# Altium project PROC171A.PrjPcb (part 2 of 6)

## Sheet PROC171_AM263P_2_Clock_Reset_Boot_JTAG.SchDoc
size 431 x 279 mm; Date: Not shown in title block; ApprovedBy: Not shown in title block; CheckedBy: Not shown in title block; Author: Not shown in title block; CompanyName: Not shown in title block; Engineer: Srinivas; Organization: Not shown in title block; Address1: Not shown in title block; Address2: Not shown in title block; Address3: Not shown in title block; Address4: Not shown in title block; DocumentNumber: 6; Revision: Use project parameter SCH_Rev; SheetNumber: 6; SheetTotal: 27; PageSetup: Record=PageOptions¦CenterHorizontal=True¦CenterVertical=True¦PrintScale=1.00¦XCorrection=1.00¦YCorrection=1.00¦PrintKind=0¦BorderSize=5000000¦LeftOffset=0¦BottomOffset=0¦Orientation=2¦PaperLength=1000¦PaperWidth=1000¦Scale=100¦PaperSource=15¦PrintQuality=600¦MediaType=1¦DitherType=10¦PaperKind=Letter¦PrintScaleMode=1
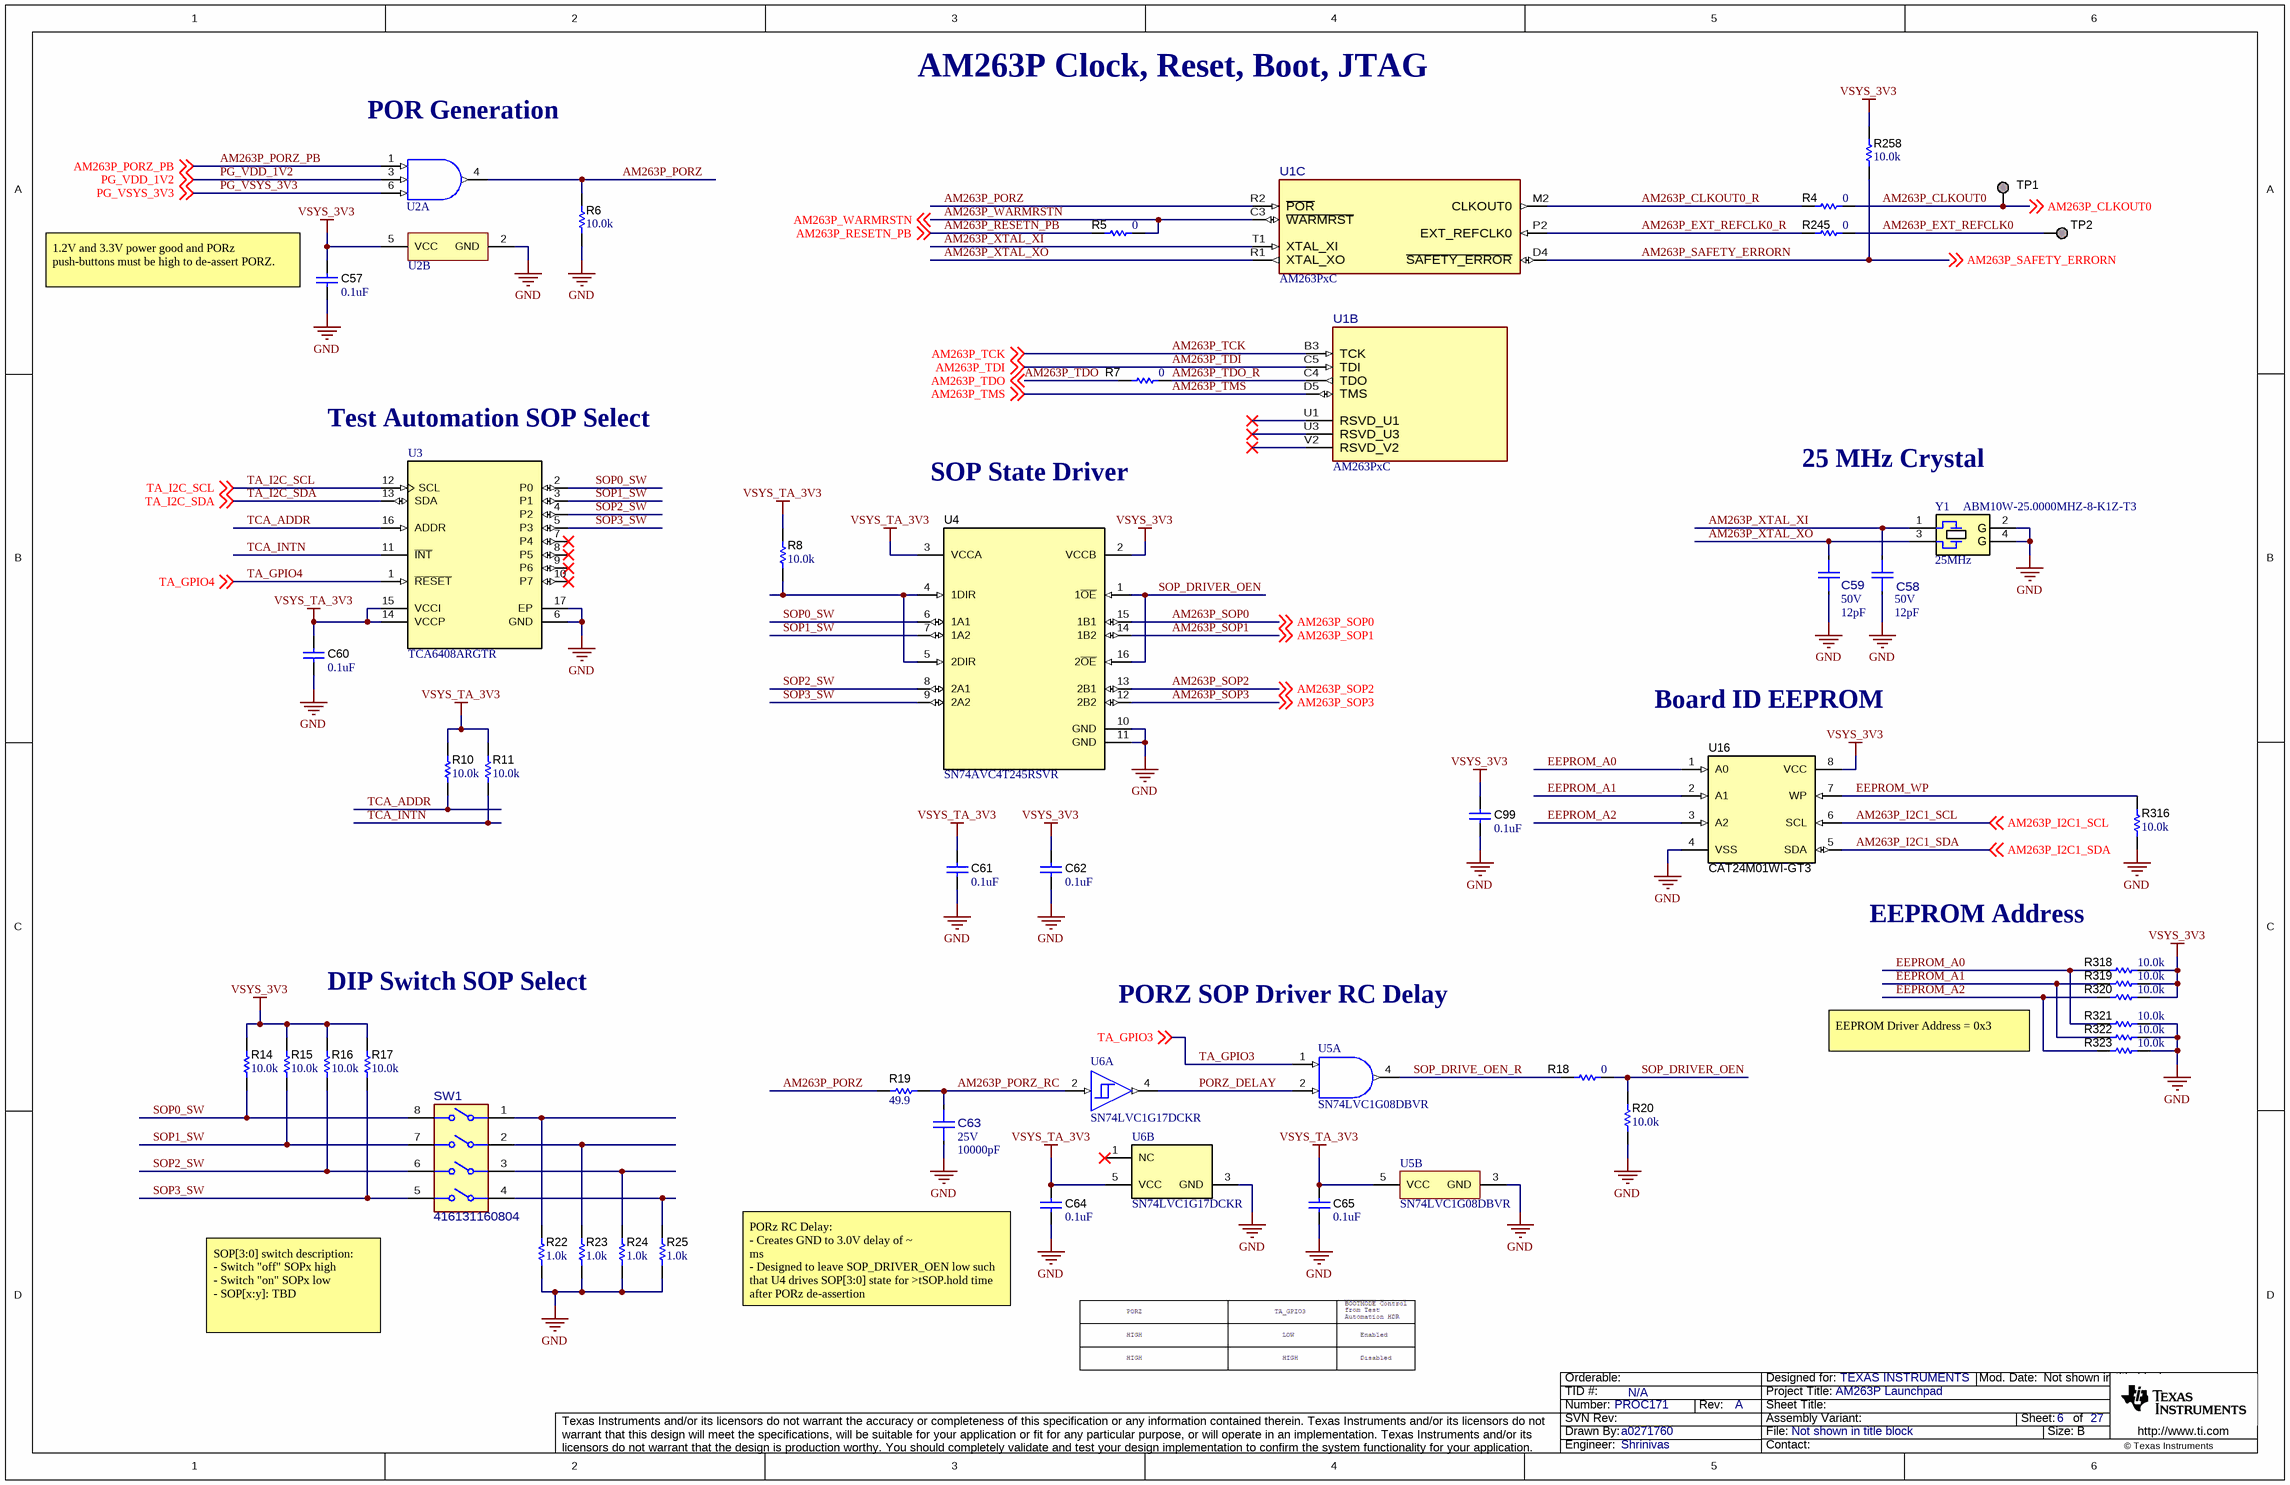
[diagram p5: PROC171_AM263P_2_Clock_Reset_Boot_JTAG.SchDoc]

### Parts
C57  ValueDisplayed: 0.1uF  [0402]  (hidden comment: GRM155R71E104KE14D)
C58  VDC_V: 50V  ValueDisplayed: 12pF  [FP-GJM1555C1H120JB01D_0402-MFG]  (hidden comment: GJM1555C1H120JB01D)
C59  VDC_V: 50V  ValueDisplayed: 12pF  [FP-GJM1555C1H120JB01D_0402-MFG]  (hidden comment: GJM1555C1H120JB01D)
C60  ValueDisplayed: 0.1uF  [0402]  (hidden comment: GRM155R71E104KE14D)
C61  ValueDisplayed: 0.1uF  [0402]  (hidden comment: GRM155R71E104KE14D)
C62  ValueDisplayed: 0.1uF  [0402]  (hidden comment: GRM155R71E104KE14D)
C63  VDC_V: 25V  ValueDisplayed: 10000pF  [FP-GRM1555C1E103JE01D_0402-MFG]  (hidden comment: GRM1555C1E103JE01D)
C64  ValueDisplayed: 0.1uF  [0402]  (hidden comment: GRM155R71E104KE14D)
C65  ValueDisplayed: 0.1uF  [0402]  (hidden comment: GRM155R71E104KE14D)
C99  ValueDisplayed: 0.1uF  [0402]  (hidden comment: GRM155R71E104KE14D)
R4  value 0  [0402L]  (hidden comment: ERJ-2GE0R00X)
R5  ValueDisplayed: 0  [0402]  (hidden comment: ERJ-2GE0R00X)
R6  ValueDisplayed: 10.0k  [0402]  (hidden comment: ERJ-2RKF1002X)
R7  value 0  [0402L]  (hidden comment: ERJ-2GE0R00X)
R8  ValueDisplayed: 10.0k  [0402]  (hidden comment: ERJ-2RKF1002X)
R10  ValueDisplayed: 10.0k  [0402]  (hidden comment: ERJ-2RKF1002X)
R11  ValueDisplayed: 10.0k  [0402]  (hidden comment: ERJ-2RKF1002X)
R14  ValueDisplayed: 10.0k  [0402]  (hidden comment: ERJ-2RKF1002X)
R15  ValueDisplayed: 10.0k  [0402]  (hidden comment: ERJ-2RKF1002X)
R16  ValueDisplayed: 10.0k  [0402]  (hidden comment: ERJ-2RKF1002X)
R17  ValueDisplayed: 10.0k  [0402]  (hidden comment: ERJ-2RKF1002X)
R18  ValueDisplayed: 0  [0402]  (hidden comment: ERJ-2GE0R00X)
R19  ValueDisplayed: 49.9  [0402]  (hidden comment: ERJ-2RKF49R9X)
R20  ValueDisplayed: 10.0k  [0402]  (hidden comment: ERJ-2RKF1002X)
R22  ValueDisplayed: 1.0k  [0402]  (hidden comment: ERJ-2GEJ102X)
R23  ValueDisplayed: 1.0k  [0402]  (hidden comment: ERJ-2GEJ102X)
R24  ValueDisplayed: 1.0k  [0402]  (hidden comment: ERJ-2GEJ102X)
R25  ValueDisplayed: 1.0k  [0402]  (hidden comment: ERJ-2GEJ102X)
R245  value 0  [0402L]  (hidden comment: ERJ-2GE0R00X)
R258  ValueDisplayed: 10.0k  [0402]  (hidden comment: ERJ-2RKF1002X)
R316  ValueDisplayed: 10.0k  [0402]  (hidden comment: ERJ-2RKF1002X)
R318  ValueDisplayed: 10.0k  [0402]  (hidden comment: ERJ-2RKF1002X)
R319  ValueDisplayed: 10.0k  [0402]  (hidden comment: ERJ-2RKF1002X)
R320  ValueDisplayed: 10.0k  [0402]  (hidden comment: ERJ-2RKF1002X)
R321  ValueDisplayed: 10.0k  [0402]  (hidden comment: ERJ-2RKF1002X)
R322  ValueDisplayed: 10.0k  [0402]  (hidden comment: ERJ-2RKF1002X)
R323  ValueDisplayed: 10.0k  [0402]  (hidden comment: ERJ-2RKF1002X)
SW1  416131160804  [FP-416131160804_SMT_SW-MFG]
TP1  TP_SM_1MM  [TP_SM_1MM]  (value not drawn)  (no BOM)
TP2  TP_SM_1MM  [TP_SM_1MM]  (value not drawn)  (no BOM)
U1  AM263PxC  [ZCZ0324A-MFG]  (parts B,C of 13)
U2  SN74LVC1G11DBVR  [DBV0006A_N]  (value not drawn)  (parts A,B of 2)
U3  TCA6408ARGTR  [RGT0016A]
U4  SN74AVC4T245RSVR  [RSV0016A]
U5  SN74LVC1G08DBVR  [DBV0005A_N]  (parts A,B of 2)
U6  SN74LVC1G17DCKR  [DCK0005A_N]  (parts A,B of 2)
U16  CAT24M01WI-GT3  [SOIC-8]
Y1  Frequency_Fixed: 25MHz  PartNumber: ABM10W-25.0000MHZ-8-K1Z-T3  [Abracon_ABM10W]  (hidden comment: ABM10W-25.0000MHZ-4-D1X-T3)

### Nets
GND: C57.1 C58.1 C59.1 C60.1 C61.1 C62.1 C63.1 C64.1 C65.1 C99.1 R6.1 R20.2 R22.1 R23.1 R24.1 R25.1 R316.2 R321.1 R322.1 R323.1 U2.2(GND) U3.6(GND) U3.17(EP) U4.10(GND) U4.11(GND) U5.3(GND) U6.3(GND) U16.4(VSS) Y1.2(GND) Y1.4(GND)
VSYS_3V3: C57.2 C62.2 C99.2 R14.1 R15.1 R16.1 R17.1 R258.2 R318.1 R319.1 R320.1 U2.5(VCC) U4.2(VCCB) U16.8(VCC)
VSYS_TA_3V3: C60.2 C61.2 C64.2 C65.2 R8.1 R10.1 R11.1 U3.14(VCCP) U3.15(VCCI) U4.3(VCCA) U5.5(VCC) U6.5(VCC)
AM263P_CLKOUT0: R4.2 TP1.1 ; off-sheet AM263P_CLKOUT0
AM263P_CLKOUT0_R: R4.1 U1.M2(CLKOUT0)
AM263P_EXT_REFCLK0: R245.2 TP2.1
AM263P_EXT_REFCLK0_R: R245.1 U1.P2(EXT_REFCLK0)
AM263P_I2C1_SCL: U16.6(SCL) ; off-sheet AM263P_I2C1_SCL
AM263P_I2C1_SDA: U16.5(SDA) ; off-sheet AM263P_I2C1_SDA
AM263P_PORZ: R6.2 R19.1 U1.R2(~{POR}) U2.4(Y)
AM263P_PORZ_PB: U2.1(A) ; off-sheet AM263P_PORZ_PB
AM263P_PORZ_RC: C63.2 R19.2 U6.2(A)
AM263P_RESETN_PB: R5.1 ; off-sheet AM263P_RESETN_PB
AM263P_SAFETY_ERRORN: R258.1 U1.D4(~{SAFETY_ERROR}) ; off-sheet AM263P_SAFETY_ERRORN
AM263P_SOP0: U4.15(1B1) ; off-sheet AM263P_SOP0
AM263P_SOP1: U4.14(1B2) ; off-sheet AM263P_SOP1
AM263P_SOP2: U4.13(2B1) ; off-sheet AM263P_SOP2
AM263P_SOP3: U4.12(2B2) ; off-sheet AM263P_SOP3
AM263P_TCK: U1.B3(TCK) ; off-sheet AM263P_TCK
AM263P_TDI: U1.C5(TDI) ; off-sheet AM263P_TDI
AM263P_TDO: R7.1 ; off-sheet AM263P_TDO
AM263P_TDO_R: R7.2 U1.C4(TDO)
AM263P_TMS: U1.D5(TMS) ; off-sheet AM263P_TMS
AM263P_WARMRSTN: R5.2 U1.C3(~{WARMRST}) ; off-sheet AM263P_WARMRSTN
AM263P_XTAL_XI: C58.2 U1.T1(XTAL_XI) Y1.1
AM263P_XTAL_XO: C59.2 U1.R1(XTAL_XO) Y1.3
EEPROM_A0: R318.2 R321.2 U16.1(A0)
EEPROM_A1: R319.2 R322.2 U16.2(A1)
EEPROM_A2: R320.2 R323.2 U16.3(A2)
EEPROM_WP: R316.1 U16.7(WP)
PG_VDD_1V2: U2.3(B) ; off-sheet PG_VDD_1V2
PG_VSYS_3V3: U2.6(C) ; off-sheet PG_VSYS_3V3
PORZ_DELAY: U5.2(B) U6.4(Y)
SOP0_SW: R14.2 SW1.8 U3.2(P0) U4.6(1A1)
SOP1_SW: R15.2 SW1.7 U3.3(P1) U4.7(1A2)
SOP2_SW: R16.2 SW1.6 U3.4(P2) U4.8(2A1)
SOP3_SW: R17.2 SW1.5 U3.5(P3) U4.9(2A2)
SOP_DRIVE_OEN_R: R18.1 U5.4(Y)
SOP_DRIVER_OEN: R18.2 R20.1 U4.1(1~{OE}) U4.16(2~{OE})
TA_GPIO3: U5.1(A) ; off-sheet TA_GPIO3
TA_GPIO4: U3.1(~{RESET}) ; off-sheet TA_GPIO4
TA_I2C_SCL: U3.12(SCL) ; off-sheet TA_I2C_SCL
TA_I2C_SDA: U3.13(SDA) ; off-sheet TA_I2C_SDA
TCA_ADDR: R10.2 U3.16(ADDR)
TCA_INTN: R11.2 U3.11(~{INT})
NetR8_2: R8.2 U4.4(1DIR) U4.5(2DIR)
NetR22_2: R22.2 SW1.1
NetR23_2: R23.2 SW1.2
NetR24_2: R24.2 SW1.3
NetR25_2: R25.2 SW1.4

Not connected (* = marked no-connect by the designer): U1 U1(RSVD_U1)* U3(RSVD_U3)* V2(RSVD_V2)*; U3 7(P4)* 8(P5)* 9(P6)* 10(P7)*; U6 1(NC)*

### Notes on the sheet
- AM263P Clock, Reset, Boot, JTAG
- (near U2) POR Generation
- (near C57) 1.2V and 3.3V power good and PORz push-buttons must be high to de-assert PORZ.
- Test Automation SOP Select
- SOP State Driver
- 25 MHz Crystal
- Board ID EEPROM
- EEPROM Address
- DIP Switch SOP Select
- PORZ SOP Driver RC Delay
- EEPROM Driver Address = 0x3
- (near C64) PORz RC Delay:
  - Creates GND to 3.0V delay of ~
  ms
  - Designed to leave SOP_DRIVER_OEN low such that U4 drives SOP[3:0] state for >tSOP.hold time after PORz de-assertion
- SOP[3:0] switch description:
  - Switch "off" SOPx high
  - Switch "on" SOPx low
  - SOP[x:y]: TBD

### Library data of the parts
C57 C60-C62 C64 C65 C99 = CMP-0006659-2: CAP, CERM, 0.1 uF, 25 V, +/- 10%, X7R, 0402; Manufacturer: MuRata; TaMin_C: -55°C; Polarized: N; SizeAreaWB_mm2: 3; U/M: EA; Value: 0.1uF; TaMax_C: 125°C; SizeZ_mm: 0.6; SizeX_mm: 1; SizeY_mm: 0.5; Value2: 25V; Cap_F: 100nF; AEC Category: Q200; Value1: Unknown
C58 C59 = CMP-0035228-1: Multi-Layer Ceramic Capacitor 12pF C0G  ±5% 0402 Paper T/R; Manufacturer: Murata; TempCo: 30ppm/°C; SizeZ_mm: 0.55mm; AEC Qualified: No
C63 = CMP-0035343-1: Chip Multilayer Ceramic Capacitors for General Purpose, 0402, 10000pF, C0G, 30ppm/°C, 5%, 25V; Manufacturer: Murata; Value: 10nF; SizeZ_mm: 0.65mm; AEC Qualified: No
R4 R7 R245 = CMP-0026992-3: RES, 0, 5%, 0.1 W, AEC-Q200 Grade 0, 0402; Manufacturer: Panasonic; Power_W: 100mW; TempCo: 600 ppm/C; Value_Code: 0000; EIA_Code: E24; SizeX_mm: 1; SizeY_mm: 0.5; SizeZ_mm: 0.6; Value2: 0.1W; AEC Qualified: Y; VDC_V: 50V; AEC Category: Q200; SizeAreaWB_mm2: 3
R5 R18 = CMP-0026992-3: RES, 0, 5%, 0.1 W, AEC-Q200 Grade 0, 0402; Manufacturer: Panasonic; Power_W: 100mW; TempCo: 600 ppm/C; Value_Code: 0000; Value: 0; EIA_Code: E24; SizeX_mm: 1; SizeY_mm: 0.5; SizeZ_mm: 0.6; Value2: 0.1W; AEC Qualified: Y; VDC_V: 50V; AEC Category: Q200; SizeAreaWB_mm2: 3
R6 R8 R10 R11 R14-R17 R20 R258 R316 R318-R323 = CMP-0026658-1: RES, 10.0 k, 1%, 0.1 W, 0402; Manufacturer: Panasonic; Power_W: 100mW; TempCo: 100 ppm/C; Value_Code: 10k0; U/M: EA; Value: 10.0k; EIA_Code: E96; Res_ohm: 10k; SizeX_mm: 1; SizeY_mm: 0.5; SizeZ_mm: 0.6; Value2: 0.1W; VDC_V: 50V; AEC Category: Q200
R19 = CMP-0026703-1: RES, 49.9, 1%, 0.1 W, AEC-Q200 Grade 0, 0402; Manufacturer: Panasonic; Power_W: 100mW; TempCo: 100 ppm/C; Value_Code: 49R9; U/M: EA; Value: 49.9; EIA_Code: E96; SizeX_mm: 1; SizeY_mm: 0.5; SizeZ_mm: 0.6; Value2: 0.1W; AEC Qualified: Y; VDC_V: 50V; AEC Grade: 0; AEC Category: Q200
R22-R25 = CMP-0078193-1: RES, 1.0 k, 5%, 0.1 W, AEC-Q200 Grade 0, 0402; Manufacturer: Panasonic; Value_Code: 1k00; SizeArea_mm2: 0.5; AEC Qualified: Y; AEC Category: Q200; Res_ohm: 1k; Value: 1.0k; SizeZ_mm: 0.6; Green_REACh: Passed; EIA_Code: E24; TempCo: 200 ppm/C; AEC Grade: 0; Power_W: 100mW; VDC_V: 50V; Value2: 0.1W; Green_Lifecycle: Active; U/M: EA; SizeX_mm: 1
SW1 = CMP-0093176-1: Dip Switch SPST 4 Position Surface Mount Slide (Standard) Actuator 25mA 24VDC; Manufacturer: Wurth; PositionCount: 4; Electromechanical Life: 1000Cycles; Circuit: 4PST; Coil Resistance_ohm: 100mΩ; VDC_V: 24V; Standoff Height: 0mm; SizeZ_mm: 2.65mm; AEC Qualified: No
TP1 TP2 = CMP-0003825-1: 1mm Test Point, SMT; Manufacturer: Any
U1 = CMP-0001698-2: Sitara™ Microcontroller; Manufacturer: Texas Instruments; SizeZ_mm: 1.4mm; Core Architecture: ARM Cortex-R5F; Data Bus Width: 32bits; Frequency_Fixed: 200MHz; Interface: I2C,SPI,UART,CAN,LIN,Ethernet,Other; Max Supply Voltage: 3.465V; Memory Size: 2MBytes; Memory Type: RAM; Min Supply Voltage: 1.14V; Number Of Cores: 1; Number Of I/Os: 140; Number Of I2C Channels: 4; Number Of Spi Channels: 5; Number Of Uart Channels: 6; Standoff Height: 0.35mm; AEC Category: Q200; CompType: IC
U2 = CMP-0051219-1: Single 3-Input Positive-AND Gate, DBV0006A, LARGE T&R; Manufacturer: Texas Instruments; Output Type: CMOS; Voltage(Nom)(V): 1.8,2.5,3.3,5; ICC @ Nom Voltage(Max)(mA): 0.01; VCC(Min)(V): 1.65; Output Drive (IOL/IOH)(Max)(mA): 32/-32; Schmitt Trigger: No; Input Type: CMOS/TTL; VCC(Max)(V): 5.5; Gate Type: AND; Rating: Catalog; tpd @ Nom Voltage(Max)(ns): 20,7.8,6.2,4.6; Bits(#): 1; F @ Nom Voltage(Max)(Mhz): 150; Logic: True; Technology Family: LVC
U3 = CMP-0043157-2: Low-Voltage 8-Bit I2C and SMBus I/O Expander, 1.65 to 5.5 V, -40 to 85 degC, 16-pin QFN (RGT), Green (RoHS & no Sb/Br); Manufacturer: Texas Instruments; # of I/Os: 8; I2C Address: 0100 00x; Reset Input: Yes; Max Frequency(kHz): 400; VCC(Max)(V): 5.5; SubFamily: I2C IO Expander; VCC(Min)(V): 1.65
U4 = CMP-0066450-2: 4-Bit Dual-Supply Bus Transceiver with Configurable Voltage-Level Shifting and 3-State Outputs, RSV0016A (UQFN-16); Alternate Manufacturer: Texas Instruments; SizeAreaWB_mm2: 10.08; SizeZ_mm: 0.55; SizeX_mm: 1.8; SizeY_mm: 2.6; SizeArea_mm2: 4.68; CompType: IC; AEC Category: Q200; AEC Qualified: N
U5 = CMP-0051588-2: Single 2-Input Positive-AND Gate, DBV0005A, LARGE T&R; Manufacturer: Texas Instruments; Logic: True; ICC @ Nom Voltage(Max)(mA): 0.01; VCC(Min)(V): 1.65; Bits(#): 1; Rating: Catalog; Schmitt Trigger: No; Voltage(Nom)(V): 1.8,2.5,3.3,5; Output Drive (IOL/IOH)(Max)(mA): 32/-32; Gate Type: AND; tpd @ Nom Voltage(Max)(ns): 4.5,6,4,5; VCC(Max)(V): 5.5; Output Type: CMOS; F @ Nom Voltage(Max)(Mhz): 150; Input Type: CMOS/TTL; Technology Family: LVC; AEC Category: Q200; AEC Qualified: N; CompType: IC
U6 = CMP-0051704-3: Single Schmitt-Trigger Buffer, DCK0005A, LARGE T&R; Manufacturer: Texas Instruments; tpd @ Nom Voltage(Max)(ns): 11,6.5,5.5,5; Bits(#): 1; VCC(Min)(V): 1.65; F @ Nom Voltage(Max)(Mhz): 150; VCC(Max)(V): 5.5; Input Type: CMOS/TTL; Sub-Family: Non-Inverting Buffer/Driver; Output Type: CMOS; Output Drive (IOL/IOH)(Max)(mA): 32/-32; 3-State Output: No; Logic: True; ICC @ Nom Voltage(Max)(mA): 0.01; Voltage(Nom)(V): 1.8,2.5,3.3,5; Rating: Catalog; Schmitt Trigger: Yes; Technology Family: LVC; AEC Category: Q200; AEC Qualified: N; CompType: IC; SizeAreaWB_mm2: 9.3; SizeArea_mm2: 4.2; SizeX_mm: 2.1; SizeY_mm: 2.0; SizeZ_mm: 1.1
U16 = CMP-0005327-2: 1024-Kb I2C CMOS Serial EEPROM, SOIC-8; Manufacturer: ON Semiconductor; SizeAreaWB_mm2: 55.131; SizeZ_mm: 1.75; SizeX_mm: 5.99; SizeY_mm: 4.9; SizeArea_mm2: 29.351
Y1 = CMP-0084811-1: Crystal, 25 MHz, 10 ppm, 4 pF, SMD; Manufacturer: Abracon Corporation; Load Capacitance: 4 pF; TaMax_C: 85°C; SizeY_mm: 2.5; SizeAreaWB_mm2: 10.5; AEC Category: Q200; Frequency Stability: 20 ppm; SizeX_mm: 2; SizeArea_mm2: 5; SizeZ_mm: 0.6; AEC Qualified: N; TaMin_C: -40°C; Frequency Tolerance: 10 ppm

## Sheet PROC171_AM263P_Serial_Connectivity.SchDoc: XDS110 JTAG/USB-to-UART Bridge
size 431 x 279 mm; Date: Not shown in title block; ApprovedBy: Not shown in title block; CheckedBy: Not shown in title block; Author: Not shown in title block; CompanyName: Not shown in title block; Engineer: Not shown in title block; Organization: Not shown in title block; Address1: Not shown in title block; Address2: Not shown in title block; Address3: Not shown in title block; Address4: Not shown in title block; DocumentNumber: 7; Revision: Use project parameter SCH_Rev; SheetNumber: 7; SheetTotal: 27; PageSetup: Record=PageOptions¦CenterHorizontal=True¦CenterVertical=True¦PrintScale=1.00¦XCorrection=1.00¦YCorrection=1.00¦PrintKind=0¦BorderSize=5000000¦LeftOffset=0¦BottomOffset=0¦Orientation=2¦PaperLength=1000¦PaperWidth=1000¦Scale=100¦PaperSource=15¦PrintQuality=600¦MediaType=1¦DitherType=10¦PaperKind=Letter¦PrintScaleMode=1
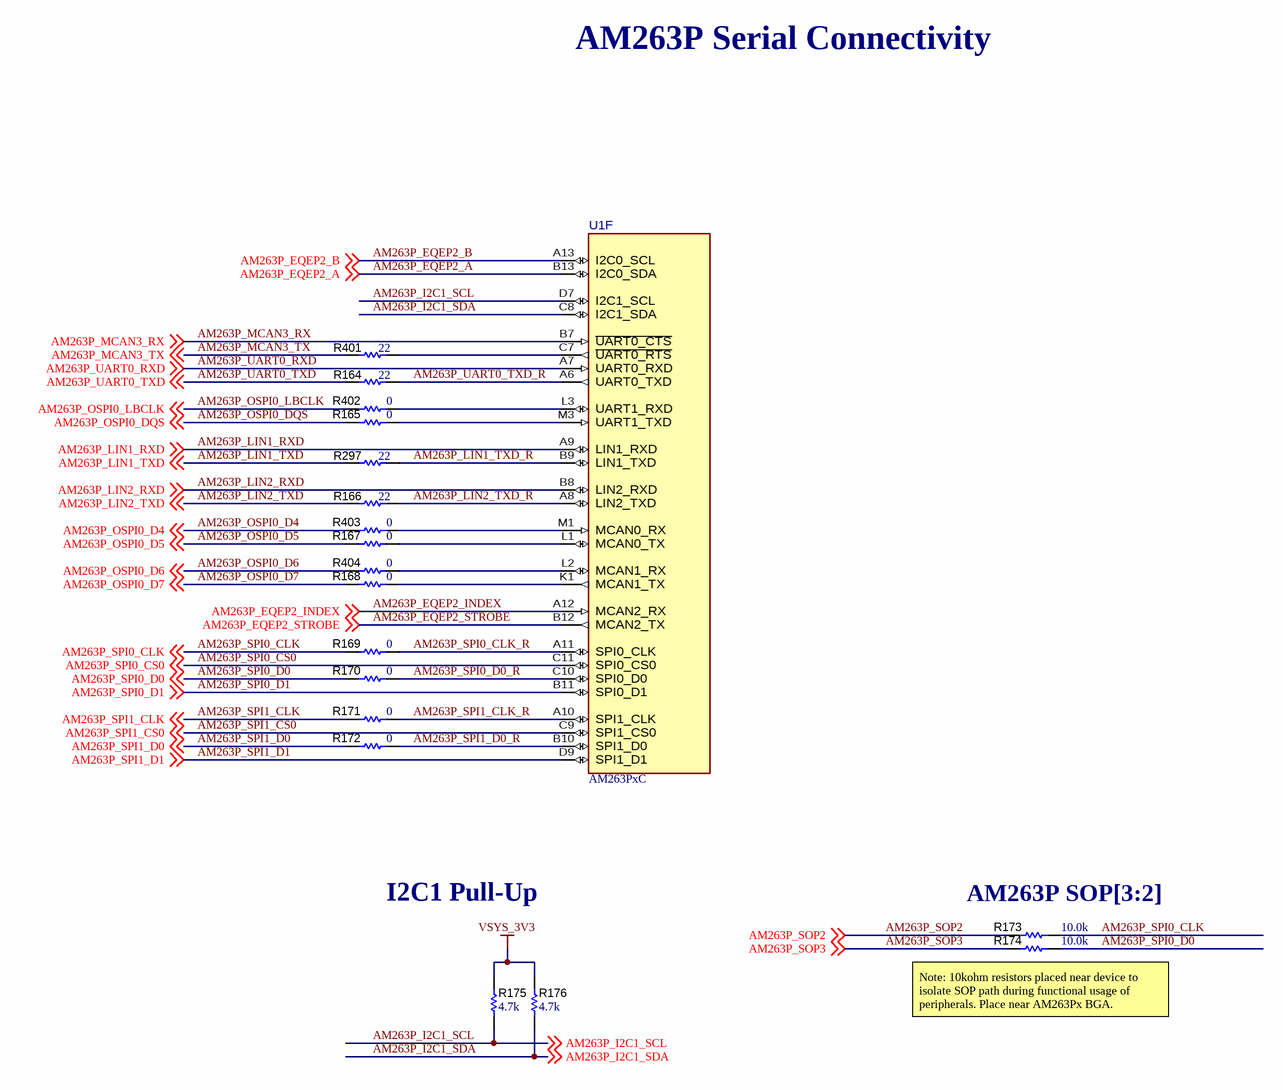
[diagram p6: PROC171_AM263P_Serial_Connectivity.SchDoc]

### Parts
R164  ValueDisplayed: 22  [0402]  (hidden comment: CRCW040222R0JNED)
R165  value 0  [0402L]  (hidden comment: ERJ-2GE0R00X)
R166  ValueDisplayed: 22  [0402]  (hidden comment: CRCW040222R0JNED)
R167  value 0  [0402L]  (hidden comment: ERJ-2GE0R00X)
R168  value 0  [0402L]  (hidden comment: ERJ-2GE0R00X)
R169  value 0  [0402L]  (hidden comment: ERJ-2GE0R00X)
R170  value 0  [0402L]  (hidden comment: ERJ-2GE0R00X)
R171  value 0  [0402L]  (hidden comment: ERJ-2GE0R00X)
R172  value 0  [0402L]  (hidden comment: ERJ-2GE0R00X)
R173  ValueDisplayed: 10.0k  [0402]  (hidden comment: ERJ-2RKF1002X)
R174  ValueDisplayed: 10.0k  [0402]  (hidden comment: ERJ-2RKF1002X)
R175  ValueDisplayed: 4.7k  [0402]  (hidden comment: CRCW04024K70JNED)
R176  ValueDisplayed: 4.7k  [0402]  (hidden comment: CRCW04024K70JNED)
R297  ValueDisplayed: 22  [0402]  (hidden comment: CRCW040222R0JNED)
R401  ValueDisplayed: 22  [0402]  (hidden comment: CRCW040222R0JNED)
R402  value 0  [0402L]  (hidden comment: ERJ-2GE0R00X)
R403  value 0  [0402L]  (hidden comment: ERJ-2GE0R00X)
R404  value 0  [0402L]  (hidden comment: ERJ-2GE0R00X)
U1  AM263PxC  [ZCZ0324A-MFG]  (part F of 13)

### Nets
VSYS_3V3: R175.2 R176.2
AM263P_EQEP2_A: U1.B13(I2C0_SDA) ; off-sheet AM263P_EQEP2_A
AM263P_EQEP2_B: U1.A13(I2C0_SCL) ; off-sheet AM263P_EQEP2_B
AM263P_EQEP2_INDEX: U1.A12(MCAN2_RX) ; off-sheet AM263P_EQEP2_INDEX
AM263P_EQEP2_STROBE: U1.B12(MCAN2_TX) ; off-sheet AM263P_EQEP2_STROBE
AM263P_I2C1_SCL: R175.1 U1.D7(I2C1_SCL) ; off-sheet AM263P_I2C1_SCL
AM263P_I2C1_SDA: R176.1 U1.C8(I2C1_SDA) ; off-sheet AM263P_I2C1_SDA
AM263P_LIN1_RXD: U1.A9(LIN1_RXD) ; off-sheet AM263P_LIN1_RXD
AM263P_LIN1_TXD: R297.1 ; off-sheet AM263P_LIN1_TXD
AM263P_LIN1_TXD_R: R297.2 U1.B9(LIN1_TXD)
AM263P_LIN2_RXD: U1.B8(LIN2_RXD) ; off-sheet AM263P_LIN2_RXD
AM263P_LIN2_TXD: R166.1 ; off-sheet AM263P_LIN2_TXD
AM263P_LIN2_TXD_R: R166.2 U1.A8(LIN2_TXD)
AM263P_MCAN3_RX: U1.B7(~{UART0_CTS}) ; off-sheet AM263P_MCAN3_RX
AM263P_MCAN3_TX: R401.1 ; off-sheet AM263P_MCAN3_TX
AM263P_OSPI0_D4: R403.1 ; off-sheet AM263P_OSPI0_D4
AM263P_OSPI0_D5: R167.1 ; off-sheet AM263P_OSPI0_D5
AM263P_OSPI0_D6: R404.1 ; off-sheet AM263P_OSPI0_D6
AM263P_OSPI0_D7: R168.1 ; off-sheet AM263P_OSPI0_D7
AM263P_OSPI0_DQS: R165.1 ; off-sheet AM263P_OSPI0_DQS
AM263P_OSPI0_LBCLK: R402.1 ; off-sheet AM263P_OSPI0_LBCLK
AM263P_SOP2: R173.2 ; off-sheet AM263P_SOP2
AM263P_SOP3: R174.2 ; off-sheet AM263P_SOP3
AM263P_SPI0_CLK: R169.1 R173.1 ; off-sheet AM263P_SPI0_CLK
AM263P_SPI0_CLK_R: R169.2 U1.A11(SPI0_CLK)
AM263P_SPI0_CS0: U1.C11(SPI0_CS0) ; off-sheet AM263P_SPI0_CS0
AM263P_SPI0_D0: R170.1 R174.1 ; off-sheet AM263P_SPI0_D0
AM263P_SPI0_D0_R: R170.2 U1.C10(SPI0_D0)
AM263P_SPI0_D1: U1.B11(SPI0_D1) ; off-sheet AM263P_SPI0_D1
AM263P_SPI1_CLK: R171.1 ; off-sheet AM263P_SPI1_CLK
AM263P_SPI1_CLK_R: R171.2 U1.A10(SPI1_CLK)
AM263P_SPI1_CS0: U1.C9(SPI1_CS0) ; off-sheet AM263P_SPI1_CS0
AM263P_SPI1_D0: R172.1 ; off-sheet AM263P_SPI1_D0
AM263P_SPI1_D0_R: R172.2 U1.B10(SPI1_D0)
AM263P_SPI1_D1: U1.D9(SPI1_D1) ; off-sheet AM263P_SPI1_D1
AM263P_UART0_RXD: U1.A7(UART0_RXD) ; off-sheet AM263P_UART0_RXD
AM263P_UART0_TXD: R164.1 ; off-sheet AM263P_UART0_TXD
AM263P_UART0_TXD_R: R164.2 U1.A6(UART0_TXD)
NetR165_2: R165.2 U1.M3(UART1_TXD)
NetR167_2: R167.2 U1.L1(MCAN0_TX)
NetR168_2: R168.2 U1.K1(MCAN1_TX)
NetR401_2: R401.2 U1.C7(~{UART0_RTS})
NetR402_2: R402.2 U1.L3(UART1_RXD)
NetR403_2: R403.2 U1.M1(MCAN0_RX)
NetR404_2: R404.2 U1.L2(MCAN1_RX)

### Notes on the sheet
- AM263P Serial Connectivity
- I2C1 Pull-Up
- AM263P SOP[3:2]
- (near R174) Note: 10kohm resistors placed near device to isolate SOP path during functional usage of peripherals. Place near AM263Px BGA.

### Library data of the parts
R164 R166 R297 R401 = CMP-0026880-3: RES, 22, 5%, 0.063 W, AEC-Q200 Grade 0, 0402; Manufacturer: Vishay-Dale; Power_W: 63mW; TempCo: 200 ppm/C; Value_Code: 22R0; Value: 22; EIA_Code: E24; SizeX_mm: 1; SizeY_mm: 0.5; SizeZ_mm: 0.6; Value2: 0.063W; AEC Qualified: Y; VDC_V: 50V; AEC Category: Q200; AEC Grade: 0
R165 R167-R172 R402-R404 = CMP-0026992-3: as R4 on sheet PROC171_AM263P_2_Clock_Reset_Boot_JTAG
R173 R174 = CMP-0026658-1: as R6 on sheet PROC171_AM263P_2_Clock_Reset_Boot_JTAG
R175 R176 = CMP-0026938-5: RES, 4.7 k, 5%, 0.063 W, AEC-Q200 Grade 0, 0402; Manufacturer: Vishay-Dale; Power_W: 63mW; TempCo: 200 ppm/C; Value_Code: 4k70; Value: 4.7k; EIA_Code: E24; SizeX_mm: 1; SizeY_mm: 0.5; SizeZ_mm: 0.6; Value2: 0.063W; AEC Qualified: Y; VDC_V: 50V; AEC Category: Q200; AEC Grade: 0
U1 = CMP-0001698-2: as U1 on sheet PROC171_AM263P_2_Clock_Reset_Boot_JTAG

## Sheet PROC171_AM263P_3_OSPI_MMC.SchDoc
size 431 x 279 mm; Date: Not shown in title block; ApprovedBy: Not shown in title block; CheckedBy: Not shown in title block; Author: Not shown in title block; CompanyName: Not shown in title block; Engineer: Not shown in title block; Organization: Not shown in title block; Address1: Not shown in title block; Address2: Not shown in title block; Address3: Not shown in title block; Address4: Not shown in title block; DocumentNumber: 8; Revision: Use project parameter SCH_Rev; SheetNumber: 8; SheetTotal: 27; PageSetup: Record=PageOptions¦CenterHorizontal=True¦CenterVertical=True¦PrintScale=1.00¦XCorrection=1.00¦YCorrection=1.00¦PrintKind=0¦BorderSize=5000000¦LeftOffset=0¦BottomOffset=0¦Orientation=2¦PaperLength=1000¦PaperWidth=1000¦Scale=100¦PaperSource=15¦PrintQuality=600¦MediaType=1¦DitherType=10¦PaperKind=Letter¦PrintScaleMode=1
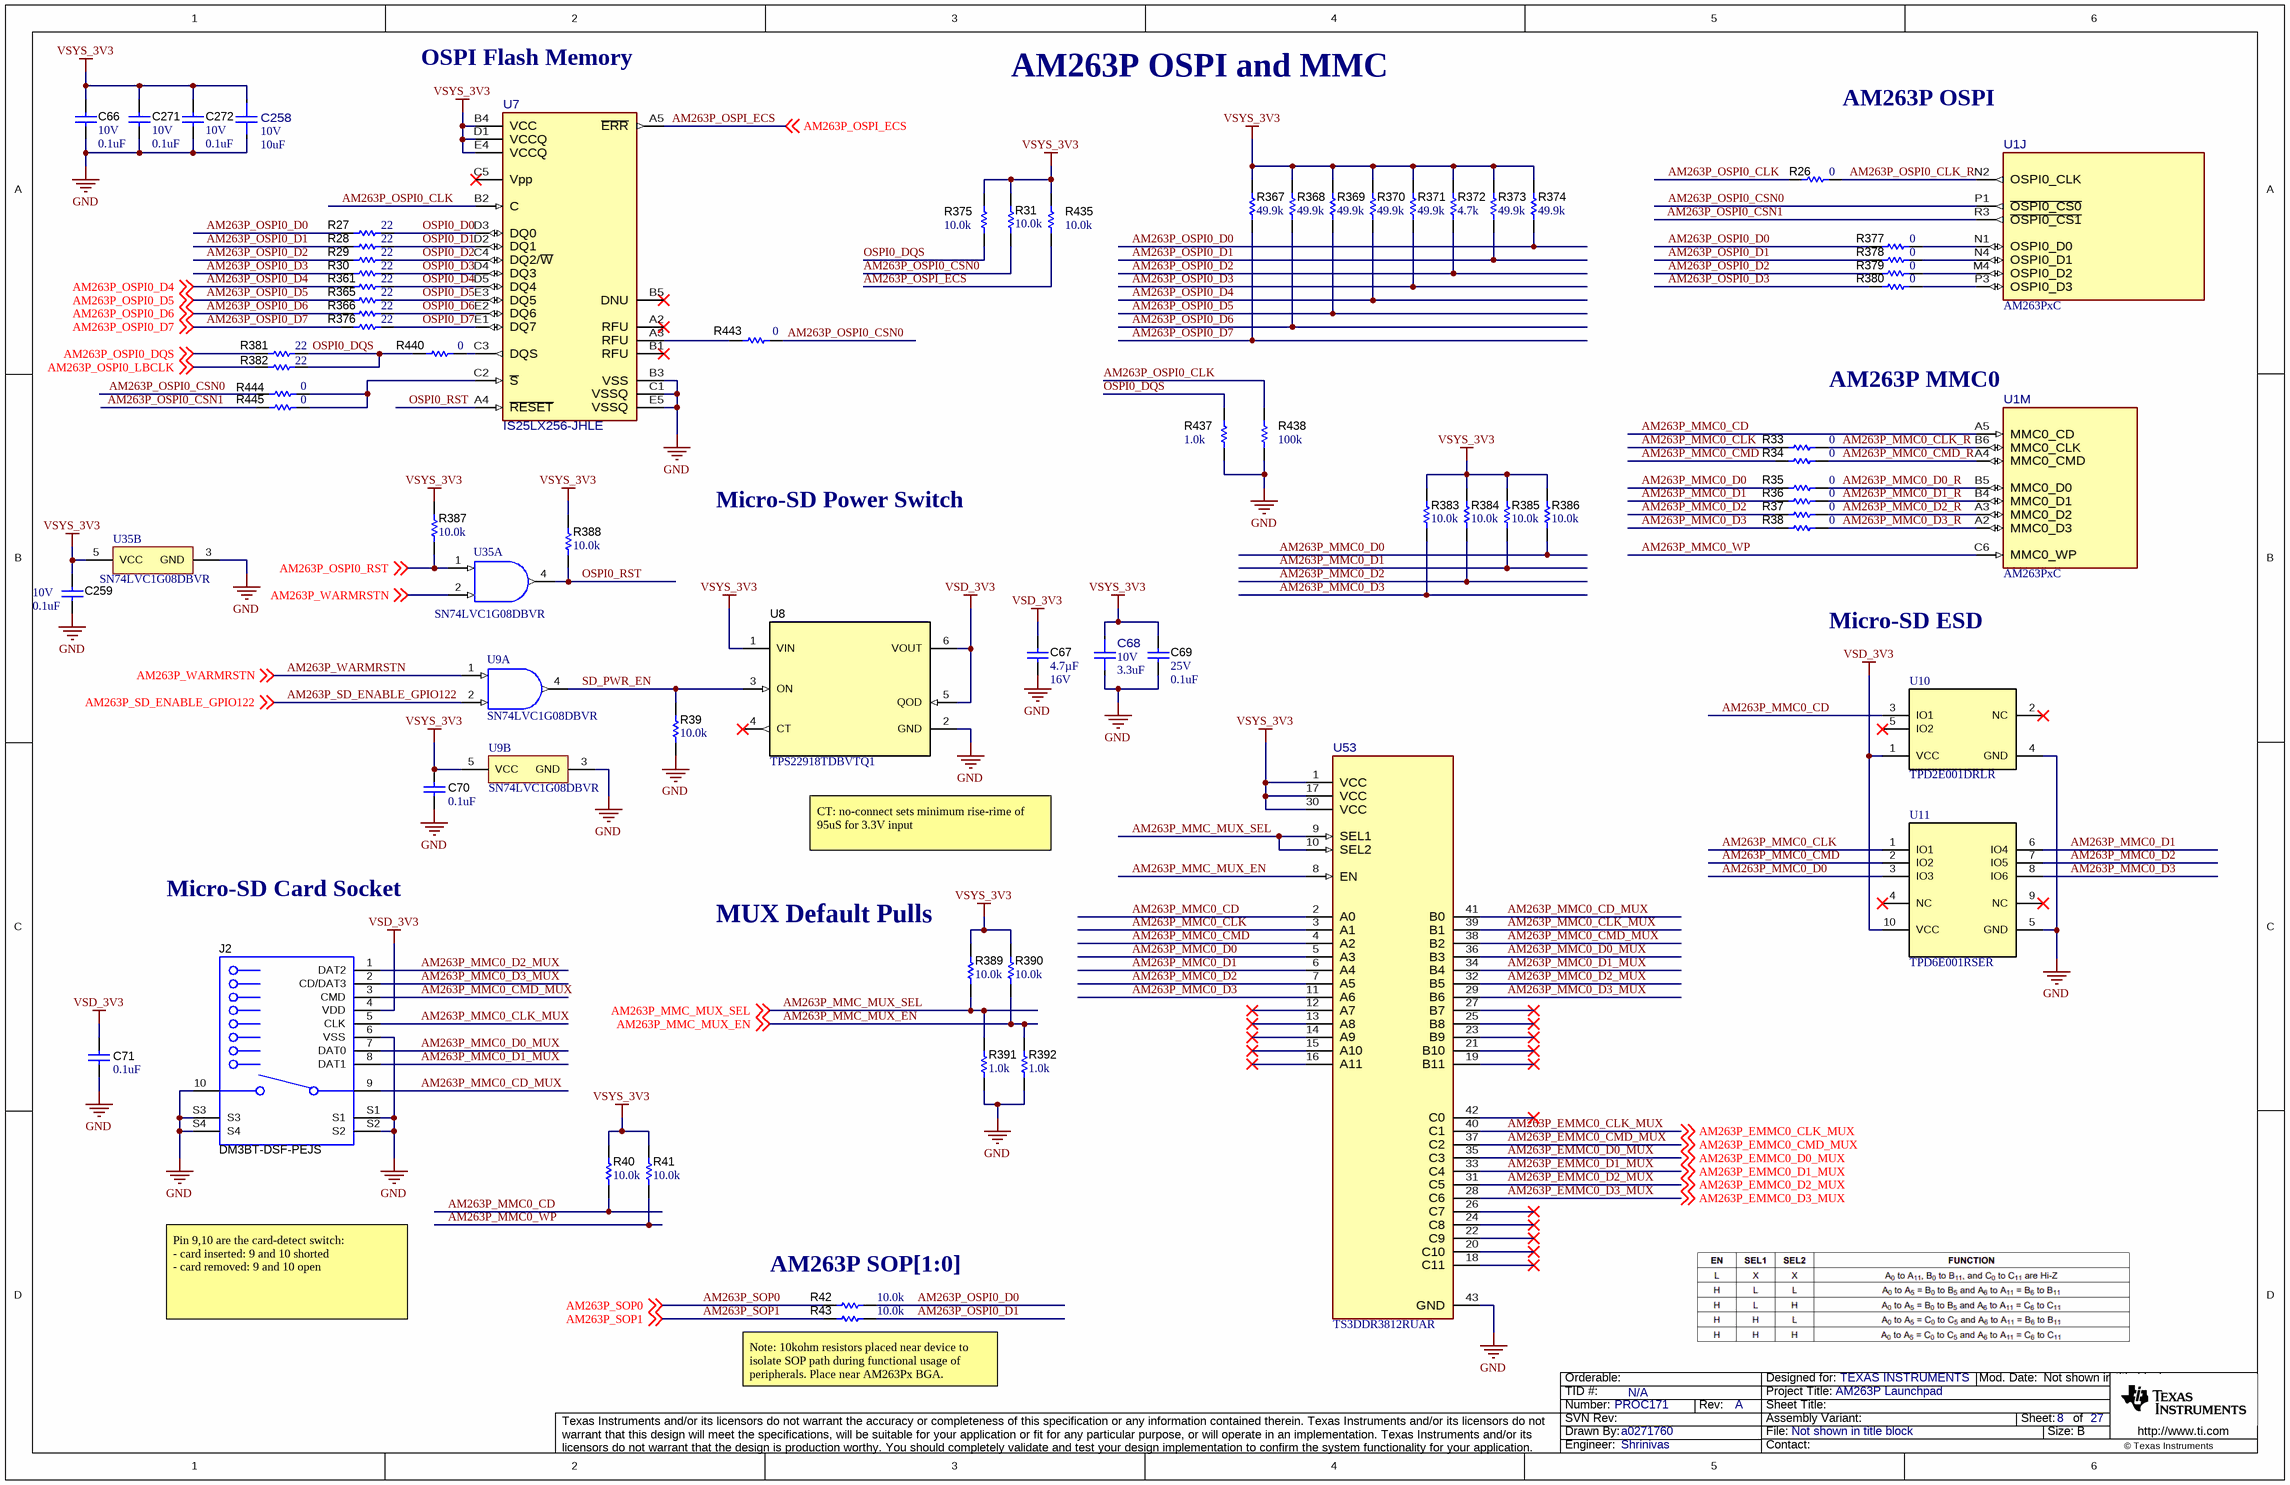
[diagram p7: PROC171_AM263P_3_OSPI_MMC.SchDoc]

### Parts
C66  VDC_V: 10V  ValueDisplayed: 0.1uF  [0402]  (hidden comment: 885012105010)
C67  Cap_F: 4.7µF  VDC_V: 16V  [0603]  (hidden comment: GRM188Z71C475KE21D)
C68  VDC_V: 10V  ValueDisplayed: 3.3uF  [FP-CL10A335KP8NNNC_0603-MFG]  (hidden comment: CL10A335KP8NNNC)
C69  VDC_V: 25V  ValueDisplayed: 0.1uF  [0402]  (hidden comment: GRM155R71E104KE14D)
C70  ValueDisplayed: 0.1uF  [0402]  (hidden comment: GRM155R71E104KE14D)
C71  ValueDisplayed: 0.1uF  [0402]  (hidden comment: GRM155R71E104KE14D)
C258  ValueDisplayed: 10uF  VDC_V: 10V  [FP-KGM05CR51A106MH_0402-MFG]  (hidden comment: KGM05CR51A106MH)
C259  VDC_V: 10V  ValueDisplayed: 0.1uF  [0402]  (hidden comment: 885012105010)
C271  VDC_V: 10V  ValueDisplayed: 0.1uF  [0402]  (hidden comment: 885012105010)
C272  VDC_V: 10V  ValueDisplayed: 0.1uF  [0402]  (hidden comment: 885012105010)
J2  DM3BT-DSF-PEJS  [Hirose_DM3BT-DSF-PEJS]
R26  value 0  [0402L]  (hidden comment: ERJ-2GE0R00X)
R27  Res_ohm: 22  [FP-CRCW020122R0FNED_0201 (0603 metric)-MFG]  (hidden comment: CRCW020122R0FNED)
R28  Res_ohm: 22  [FP-CRCW020122R0FNED_0201 (0603 metric)-MFG]  (hidden comment: CRCW020122R0FNED)
R29  Res_ohm: 22  [FP-CRCW020122R0FNED_0201 (0603 metric)-MFG]  (hidden comment: CRCW020122R0FNED)
R30  Res_ohm: 22  [FP-CRCW020122R0FNED_0201 (0603 metric)-MFG]  (hidden comment: CRCW020122R0FNED)
R31  ValueDisplayed: 10.0k  [0402L]  (hidden comment: CRCW040210K0FKED)
R33  ValueDisplayed: 0  [0402L]  (hidden comment: ERJ-2GE0R00X)
R34  ValueDisplayed: 0  [0402L]  (hidden comment: ERJ-2GE0R00X)
R35  ValueDisplayed: 0  [0402L]  (hidden comment: ERJ-2GE0R00X)
R36  ValueDisplayed: 0  [0402L]  (hidden comment: ERJ-2GE0R00X)
R37  ValueDisplayed: 0  [0402L]  (hidden comment: ERJ-2GE0R00X)
R38  ValueDisplayed: 0  [0402L]  (hidden comment: ERJ-2GE0R00X)
R39  ValueDisplayed: 10.0k  [0402L]  (hidden comment: CRCW040210K0FKED)
R40  ValueDisplayed: 10.0k  [0402L]  (hidden comment: CRCW040210K0FKED)
R41  ValueDisplayed: 10.0k  [0402L]  (hidden comment: CRCW040210K0FKED)
R42  ValueDisplayed: 10.0k  [0402]  (hidden comment: ERJ-2RKF1002X)
R43  ValueDisplayed: 10.0k  [0402]  (hidden comment: ERJ-2RKF1002X)
R361  Res_ohm: 22  [FP-CRCW020122R0FNED_0201 (0603 metric)-MFG]  (hidden comment: CRCW020122R0FNED)
R365  Res_ohm: 22  [FP-CRCW020122R0FNED_0201 (0603 metric)-MFG]  (hidden comment: CRCW020122R0FNED)
R366  Res_ohm: 22  [FP-CRCW020122R0FNED_0201 (0603 metric)-MFG]  (hidden comment: CRCW020122R0FNED)
R367  ValueDisplayed: 49.9k  [0402]  (hidden comment: ERJ-2RKF4992X)
R368  ValueDisplayed: 49.9k  [0402]  (hidden comment: ERJ-2RKF4992X)
R369  ValueDisplayed: 49.9k  [0402]  (hidden comment: ERJ-2RKF4992X)
R370  ValueDisplayed: 49.9k  [0402]  (hidden comment: ERJ-2RKF4992X)
R371  ValueDisplayed: 49.9k  [0402]  (hidden comment: ERJ-2RKF4992X)
R372  ValueDisplayed: 4.7k  [0402]  (hidden comment: CRCW04024K70JNED)
R373  ValueDisplayed: 49.9k  [0402]  (hidden comment: ERJ-2RKF4992X)
R374  ValueDisplayed: 49.9k  [0402]  (hidden comment: ERJ-2RKF4992X)
R375  ValueDisplayed: 10.0k  [0402L]  (hidden comment: CRCW040210K0FKED)
R376  Res_ohm: 22  [FP-CRCW020122R0FNED_0201 (0603 metric)-MFG]  (hidden comment: CRCW020122R0FNED)
R377  value 0  [0402L]  (hidden comment: ERJ-2GE0R00X)
R378  value 0  [0402L]  (hidden comment: ERJ-2GE0R00X)
R379  value 0  [0402L]  (hidden comment: ERJ-2GE0R00X)
R380  value 0  [0402L]  (hidden comment: ERJ-2GE0R00X)
R381  Res_ohm: 22  [FP-CRCW020122R0FNED_0201 (0603 metric)-MFG]  (hidden comment: CRCW020122R0FNED)
R382  ValueDisplayed: 22  [0402]  (hidden comment: CRCW040222R0JNED)
R383  ValueDisplayed: 10.0k  [0402L]  (hidden comment: CRCW040210K0FKED)
R384  ValueDisplayed: 10.0k  [0402L]  (hidden comment: CRCW040210K0FKED)
R385  ValueDisplayed: 10.0k  [0402L]  (hidden comment: CRCW040210K0FKED)
R386  ValueDisplayed: 10.0k  [0402L]  (hidden comment: CRCW040210K0FKED)
R387  ValueDisplayed: 10.0k  [0402L]  (hidden comment: CRCW040210K0FKED)
R388  ValueDisplayed: 10.0k  [0402L]  (hidden comment: CRCW040210K0FKED)
R389  ValueDisplayed: 10.0k  [0402]  (hidden comment: ERJ-2RKF1002X)
R390  ValueDisplayed: 10.0k  [0402]  (hidden comment: ERJ-2RKF1002X)
R391  ValueDisplayed: 1.0k  [0402]  (hidden comment: ERJ-2GEJ102X)
R392  ValueDisplayed: 1.0k  [0402]  (hidden comment: ERJ-2GEJ102X)
R435  ValueDisplayed: 10.0k  [0402L]  (hidden comment: CRCW040210K0FKED)
R437  ValueDisplayed: 1.0k  [0402]  (hidden comment: ERJ-2GEJ102X)
R438  ValueDisplayed: 100k  [0402]  (hidden comment: ERJ-2RKF1003X)
R440  ValueDisplayed: 0  [0402L]  (hidden comment: ERJ-2GE0R00X)
R443  value 0  [0402L]  (hidden comment: ERJ-2GE0R00X)
R444  ValueDisplayed: 0  [0402L]  (hidden comment: ERJ-2GE0R00X)
R445  ValueDisplayed: 0  [0402L]  (hidden comment: ERJ-2GE0R00X)
U1  AM263PxC  [ZCZ0324A-MFG]  (parts J,M of 13)
U7  IS25LX256-JHLE  [FP-IS25LX256-JHLE_TFBGA24-IPC_C]
U8  TPS22918TDBVTQ1  [DBV0006A_N]
U9  SN74LVC1G08DBVR  [DBV0005A_N]  (parts A,B of 2)
U10  TPD2E001DRLR  [DRL0005A]
U11  TPD6E001RSER  [RSE0010A]
U35  SN74LVC1G08DBVR  [DBV0005A_N]  (parts A,B of 2)
U53  TS3DDR3812RUAR  [RUA0042A-MFG]

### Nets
GND: C66.2 C67.2 C68.2 C69.2 C70.1 C71.1 C258.2 C259.2 C271.2 C272.2 J2.6(VSS) J2.10(B) J2.S1 J2.S2 J2.S3 J2.S4 R39.1 R391.1 R392.1 R437.1 R438.1 U7.B3(VSS) U7.C1(VSSQ) U7.E5(VSSQ) U8.2(GND) U9.3(GND) U10.4(GND) U11.5(GND) U35.3(GND) U53.43(GND)
VSD_3V3: C67.1 C71.2 J2.4(VDD) U8.5(QOD) U8.6(VOUT) U10.1(VCC) U11.10(VCC)
VSYS_3V3: C66.1 C68.1 C69.1 C70.2 C258.1 C259.1 C271.1 C272.1 R31.1 R40.2 R41.2 R367.1 R368.1 R369.1 R370.1 R371.1 R372.2 R373.1 R374.1 R375.2 R383.2 R384.2 R385.2 R386.2 R387.2 R388.2 R389.1 R390.1 R435.2 U7.B4(VCC) U7.D1(VCCQ) U7.E4(VCCQ) U8.1(VIN) U9.5(VCC) U35.5(VCC) U53.1(VCC) U53.17(VCC) U53.30(VCC)
AM263P_EMMC0_CLK_MUX: U53.40(C1) ; off-sheet AM263P_EMMC0_CLK_MUX
AM263P_EMMC0_CMD_MUX: U53.37(C2) ; off-sheet AM263P_EMMC0_CMD_MUX
AM263P_EMMC0_D0_MUX: U53.35(C3) ; off-sheet AM263P_EMMC0_D0_MUX
AM263P_EMMC0_D1_MUX: U53.33(C4) ; off-sheet AM263P_EMMC0_D1_MUX
AM263P_EMMC0_D2_MUX: U53.31(C5) ; off-sheet AM263P_EMMC0_D2_MUX
AM263P_EMMC0_D3_MUX: U53.28(C6) ; off-sheet AM263P_EMMC0_D3_MUX
AM263P_MMC0_CD: R40.1 U1.A5(MMC0_CD) U10.3(IO1) U53.2(A0)
AM263P_MMC0_CD_MUX: J2.9(A) U53.41(B0)
AM263P_MMC0_CLK: R33.2 U11.1(IO1) U53.3(A1)
AM263P_MMC0_CLK_MUX: J2.5(CLK) U53.39(B1)
AM263P_MMC0_CLK_R: R33.1 U1.B6(MMC0_CLK)
AM263P_MMC0_CMD: R34.2 U11.2(IO2) U53.4(A2)
AM263P_MMC0_CMD_MUX: J2.3(CMD) U53.38(B2)
AM263P_MMC0_CMD_R: R34.1 U1.A4(MMC0_CMD)
AM263P_MMC0_D0: R35.2 R386.1 U11.3(IO3) U53.5(A3)
AM263P_MMC0_D0_MUX: J2.7(DAT0) U53.36(B3)
AM263P_MMC0_D0_R: R35.1 U1.B5(MMC0_D0)
AM263P_MMC0_D1: R36.2 R385.1 U11.6(IO4) U53.6(A4)
AM263P_MMC0_D1_MUX: J2.8(DAT1) U53.34(B4)
AM263P_MMC0_D1_R: R36.1 U1.B4(MMC0_D1)
AM263P_MMC0_D2: R37.2 R384.1 U11.7(IO5) U53.7(A5)
AM263P_MMC0_D2_MUX: J2.1(DAT2) U53.32(B5)
AM263P_MMC0_D2_R: R37.1 U1.A3(MMC0_D2)
AM263P_MMC0_D3: R38.2 R383.1 U11.8(IO6) U53.11(A6)
AM263P_MMC0_D3_MUX: J2.2(CD/DAT3) U53.29(B6)
AM263P_MMC0_D3_R: R38.1 U1.A2(MMC0_D3)
AM263P_MMC0_WP: R41.1 U1.C6(MMC0_WP)
AM263P_MMC_MUX_EN: R390.2 R392.2 U53.8(EN) ; off-sheet AM263P_MMC_MUX_EN
AM263P_MMC_MUX_SEL: R389.2 R391.2 U53.9(SEL1) U53.10(SEL2) ; off-sheet AM263P_MMC_MUX_SEL
AM263P_OSPI0_CLK: R26.1 R438.2 U7.B2(C)
AM263P_OSPI0_CLK_R: R26.2 U1.N2(OSPI0_CLK)
AM263P_OSPI0_CSN0: R31.2 R443.2 R444.2 U1.P1(~{OSPI0_CS0})
AM263P_OSPI0_CSN1: R445.2 U1.R3(~{OSPI0_CS1})
AM263P_OSPI0_D0: R27.1 R42.1 R374.2 R377.1
AM263P_OSPI0_D1: R28.1 R43.1 R373.2 R378.1
AM263P_OSPI0_D2: R29.1 R372.1 R379.1
AM263P_OSPI0_D3: R30.1 R371.2 R380.1
AM263P_OSPI0_D4: R361.1 R370.2 ; off-sheet AM263P_OSPI0_D4
AM263P_OSPI0_D5: R365.1 R369.2 ; off-sheet AM263P_OSPI0_D5
AM263P_OSPI0_D6: R366.1 R368.2 ; off-sheet AM263P_OSPI0_D6
AM263P_OSPI0_D7: R367.2 R376.1 ; off-sheet AM263P_OSPI0_D7
AM263P_OSPI0_DQS: R381.1 ; off-sheet AM263P_OSPI0_DQS
AM263P_OSPI0_LBCLK: R382.1 ; off-sheet AM263P_OSPI0_LBCLK
AM263P_OSPI0_RST: R387.1 U35.1(A) ; off-sheet AM263P_OSPI0_RST
AM263P_OSPI_ECS: R435.1 U7.A5(~{ERR}) ; off-sheet AM263P_OSPI_ECS
AM263P_SD_ENABLE_GPIO122: U9.2(B) ; off-sheet AM263P_SD_ENABLE_GPIO122
AM263P_SOP0: R42.2 ; off-sheet AM263P_SOP0
AM263P_SOP1: R43.2 ; off-sheet AM263P_SOP1
AM263P_WARMRSTN: U9.1(A) U35.2(B) ; off-sheet AM263P_WARMRSTN
OSPI0_D0: R27.2 U7.D3(DQ0)
OSPI0_D1: R28.2 U7.D2(DQ1)
OSPI0_D2: R29.2 U7.C4(DQ2/~{W})
OSPI0_D3: R30.2 U7.D4(DQ3)
OSPI0_D4: R361.2 U7.D5(DQ4)
OSPI0_D5: R365.2 U7.E3(DQ5)
OSPI0_D6: R366.2 U7.E2(DQ6)
OSPI0_D7: R376.2 U7.E1(DQ7)
OSPI0_DQS: R375.1 R381.2 R382.2 R437.2 R440.2
OSPI0_RST: R388.1 U7.A4(~{RESET}) U35.4(Y)
SD_PWR_EN: R39.2 U8.3(ON) U9.4(Y)
NetR377_2: R377.2 U1.N1(OSPI0_D0)
NetR378_2: R378.2 U1.N4(OSPI0_D1)
NetR379_2: R379.2 U1.M4(OSPI0_D2)
NetR380_2: R380.2 U1.P3(OSPI0_D3)
NetR440_1: R440.1 U7.C3(DQS)
NetR443_1: R443.1 U7.A3(RFU)
NetR444_1: R444.1 R445.1 U7.C2(~{S})

Not connected (* = marked no-connect by the designer): U7 A2(RFU)* B1(RFU)* B5(DNU)* C5(Vpp)*; U8 4(CT)*; U10 2(NC)* 5(IO2)*; U11 4(NC)* 9(NC)*; U53 12(A7)* 13(A8)* 14(A9)* 15(A10)* 16(A11)* 18(C11)* 19(B11)* 20(C10)* 21(B10)* 22(C9)* 23(B9)* 24(C8)* 25(B8)* 26(C7)* 27(B7)* 42(C0)*

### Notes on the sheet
- OSPI Flash Memory
- AM263P OSPI and MMC
- AM263P OSPI
- AM263P MMC0
- Micro-SD Power Switch
- Micro-SD ESD
- Micro-SD Card Socket
- CT: no-connect sets minimum rise-rime of 95uS for 3.3V input
- (near R389) MUX Default Pulls
- AM263P SOP[1:0]
- Pin 9,10 are the card-detect switch:
  - card inserted: 9 and 10 shorted
  - card removed: 9 and 10 open
- (near R43) Note: 10kohm resistors placed near device to isolate SOP path during functional usage of peripherals. Place near AM263Px BGA.

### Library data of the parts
C66 C259 C271 C272 = CMP-0006221-2: CAP, CERM, 0.1 uF, 10 V, +/- 20%, X5R, 0402; Manufacturer: Wurth Elektronik; TaMin_C: -55°C; Polarized: N; SizeAreaWB_mm2: 3; Value1: Unknown; U/M: EA; Value: 0.1uF; TaMax_C: 85°C; SizeZ_mm: 0.6; SizeX_mm: 1; SizeY_mm: 0.5; Cap_F: 100nF; AEC Category: Q200
C67 = CMP-0064936-4: CAP, CERM, 4.7 uF, 16 V,+/- 10%, X7R, 0603; Manufacturer: MuRata; TaMin_C: -55°C; Polarized: N; SizeAreaWB_mm2: 4.68; Value1: Unknown; U/M: EA; Value: 4.7uF; TaMax_C: 125°C; SizeZ_mm: 1; SizeX_mm: 1.6; SizeY_mm: 0.8; SizeArea_mm2: 1.28; AEC Category: Q200
C68 = CMP-0042976-1: Cap Ceramic 3.3uF 10V X5R ±10% Pad SMD 0603 +85°C T/R; Manufacturer: Samsung; TempCo: 15%; Value: 3.3µF; SizeZ_mm: 0.9mm; AEC Qualified: No
C69 = CMP-0006659-2: CAP, CERM, 0.1 uF, 25 V, +/- 10%, X7R, 0402; Manufacturer: MuRata; TaMin_C: -55°C; Polarized: N; SizeAreaWB_mm2: 3; Value1: Unknown; U/M: EA; Value: 0.1uF; TaMax_C: 125°C; SizeZ_mm: 0.6; SizeX_mm: 1; SizeY_mm: 0.5; Cap_F: 100nF; AEC Category: Q200
C70 C71 = CMP-0006659-2: as C57 on sheet PROC171_AM263P_2_Clock_Reset_Boot_JTAG
C258 = CMP-0043010-1: 10 µF ±20% 10V Ceramic Capacitor X5R 0402 (1005 Metric); Manufacturer: KYOCERA AVX; AEC Qualified: No; Cap_F: 10µF; SizeZ_mm: 0.7mm; TempCo: 15%; Value: 10µF
J2 = CMP-0080007-1: Conncetor, micro SD, 8+2 Pos, R/A, SMT; Manufacturer: Hirose Electric Co. Ltd.; Pitch_mm: 1.1; Gender: Female; ContactFinish: Gold; Row_Count: 1; CompType: Connector
R26 R377-R380 R443 = CMP-0026992-3: as R4 on sheet PROC171_AM263P_2_Clock_Reset_Boot_JTAG
R27-R30 R361 R365 R366 R376 R381 = CMP-0087090-2: RES Thick Film SMD 22Ω 1% 1/20W 0201 200ppm/°C; Manufacturer: Vishay; SizeZ_mm: 0.28mm; VDC_V: 30V; Power_W: 50mW; AEC Qualified: No
R31 R39-R41 R375 R383-R388 R435 = CMP-0025958-3: RES, 10.0 k, 1%, 0.063 W, AEC-Q200 Grade 0, 0402; Manufacturer: Vishay-Dale; Power_W: 63mW; TempCo: 100 ppm/C; Value_Code: 10k0; Value: 10.0k; EIA_Code: E96; Res_ohm: 10k; SizeX_mm: 1; SizeY_mm: 0.5; SizeZ_mm: 0.6; Value2: 0.063W; AEC Qualified: Y; VDC_V: 50V; AEC Category: Q200; AEC Grade: 0
R33-R38 R440 R444 R445 = CMP-0026992-3: as R5 on sheet PROC171_AM263P_2_Clock_Reset_Boot_JTAG
R42 R43 R389 R390 = CMP-0026658-1: as R6 on sheet PROC171_AM263P_2_Clock_Reset_Boot_JTAG
R367-R371 R373 R374 = CMP-0026702-1: RES, 49.9 k, 1%, 0.1 W, AEC-Q200 Grade 0, 0402; Manufacturer: Panasonic; Power_W: 100mW; TempCo: 100 ppm/C; Value_Code: 49k9; U/M: EA; Value: 49.9k; EIA_Code: E96; SizeX_mm: 1; SizeY_mm: 0.5; SizeZ_mm: 0.6; Value2: 0.1W; AEC Qualified: Y; VDC_V: 50V; AEC Grade: 0; AEC Category: Q200
R372 = CMP-0026938-5: as R175 on sheet PROC171_AM263P_Serial_Connectivity
R382 = CMP-0026880-3: as R164 on sheet PROC171_AM263P_Serial_Connectivity
R391 R392 R437 = CMP-0078193-1: as R22-R25 on sheet PROC171_AM263P_2_Clock_Reset_Boot_JTAG
R438 = CMP-0026659-2: RES, 100 k, 1%, 0.1 W, 0402; Manufacturer: Panasonic; U/M: EA; Value2: 0.1W; EIA_Code: E96; Value: 100k; SizeArea_mm2: 0.5; TempCo: 100 ppm/C; SizeZ_mm: 0.6; AEC Category: Q200; VDC_V: 50V; Power_W: 100mW; AEC Grade: 0; SizeX_mm: 1; AEC Qualified: Yes
U1 = CMP-0001698-2: as U1 on sheet PROC171_AM263P_2_Clock_Reset_Boot_JTAG
U7 = CMP-0125522-1: FLASH Memory IC 256Mbit SPI - Octal I/O 133 MHz 6 ns 24-TFBGA (6x8); Manufacturer: ISSI; SizeZ_mm: 1.2mm; Access Time: 6ns; Frequency_Fixed: 133MHz; Max Supply Voltage: 3.6V; Min Supply Voltage: 2.7V; Nominal Supply Current: 0.13-48mA; Standoff Height: 0.26mm; TaMax_C: +105°C; TaMin_C: -40°C
U8 = CMP-0081995-1: 5.5V, 2A, 52mΩ Automotive High-Side Load Switch with Adjustable Rise Time & Quick Output Discharge, DBV0006A (SOT-23-6); Alternate PartNumber: TPS22918TDBVRQ1; Alternate Manufacturer: Texas Instruments; SizeAreaWB_mm2: 14.82; SizeZ_mm: 1.45; SizeX_mm: 2.8; SizeY_mm: 2.9; SizeArea_mm2: 8.12; CompType: IC; AEC Qualified: Y; AEC Category: Q200
U9 U35 = CMP-0051588-2: as U5 on sheet PROC171_AM263P_2_Clock_Reset_Boot_JTAG
U10 = CMP-0043096-2: Low-Capacitance + / - 15 kV ESD-Protection Array for High-Speed Data Interfaces, 2 Channels, -40 to +85 degC, 5-pin SOT (DRL), Green (RoHS & no Sb/Br); Manufacturer: Texas Instruments; IO Leakage Current(nA): 1; IO Capacitance(Typ)(pF): 1.5; USB High Speed: TRUE; SubFamily: ESD Solution; Breakdown Voltage(Min)(V): 11; IEC 61000-4-2 Air-Gap(+/- kV): 15; IEC 61000-4-2 Contact(+/- kV): 8
U11 = CMP-0043123-1: Low-Capacitance + / - 15 kV ESD Protection Array for High-Speed Data Interfaces, 6 Channels, -40 to +85 degC, 10-pin UQFN (RSE), Green (RoHS & no Sb/Br); Manufacturer: Texas Instruments; Serial ATA / eSATA: TRUE; IO Leakage Current(nA): 1; IO Capacitance(Typ)(pF): 1.5; IEC 61000-4-2 Contact(+/- kV): 8; Breakdown Voltage(Min)(V): 11; IEC 61000-4-2 Air-Gap(+/- kV): 15; SubFamily: ESD Solution
U53 = CMP-0093539-2: IC MUX/DEMUX DDR3 1:2 42WQFN; Manufacturer: Texas Instruments; TaMax_C: +85°C; TaMin_C: -40°C; On State Resistance: 8Ω; SizeZ_mm: 0.8mm; Min Supply Voltage: 3V; Standoff Height: 0mm; Max Supply Voltage: 3.6V; AEC Qualified: No; PositionCount: 12; -3Db Bandwith: 1.675GHz; Nominal Supply Current: 300uA; AEC Category: Q200

## Sheet PROC171_AM263P_4_EMMC.SchDoc
size 431 x 279 mm; DocumentNumber: 9; SheetNumber: 9; SheetTotal: 27
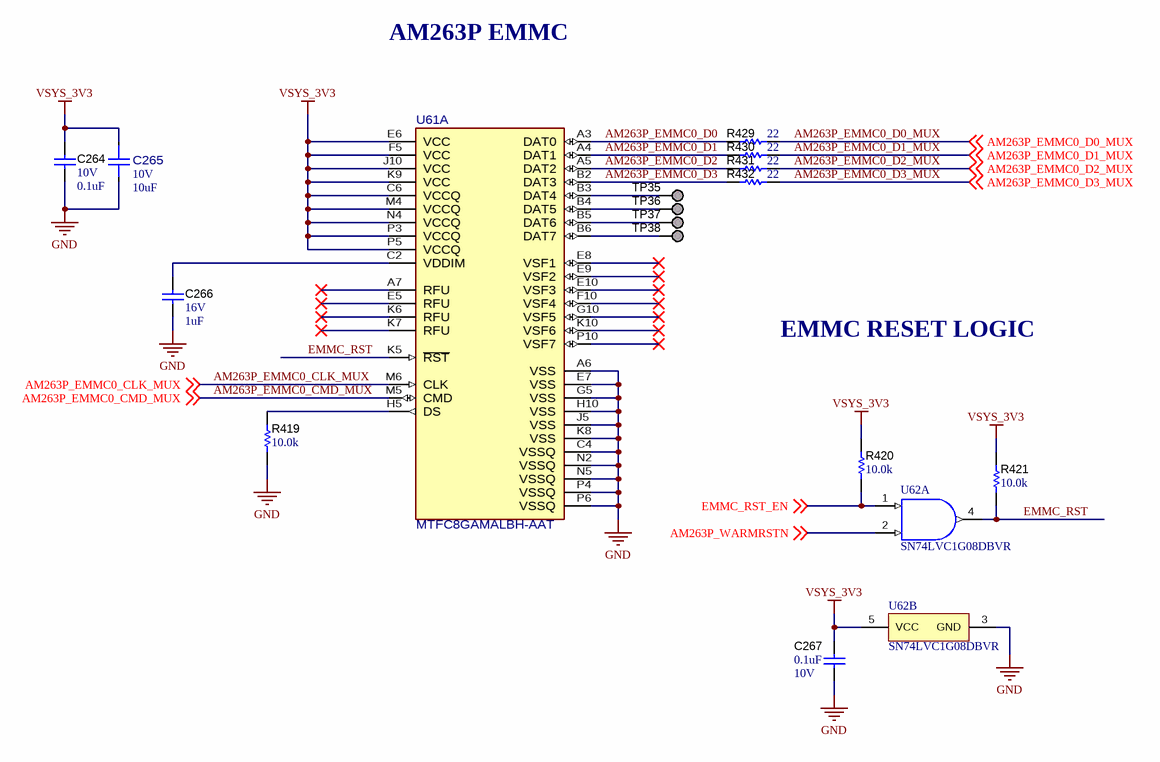
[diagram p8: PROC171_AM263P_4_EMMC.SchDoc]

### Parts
C264  VDC_V: 10V  ValueDisplayed: 0.1uF  [0402]  (hidden comment: 885012105010)
C265  ValueDisplayed: 10uF  VDC_V: 10V  [FP-KGM05CR51A106MH_0402-MFG]  (hidden comment: KGM05CR51A106MH)
C266  VDC_V: 16V  ValueDisplayed: 1uF  [0402]  (hidden comment: C1005X6S1C105K050BC)
C267  VDC_V: 10V  ValueDisplayed: 0.1uF  [0402]  (hidden comment: 885012105010)
R419  ValueDisplayed: 10.0k  [0402]  (hidden comment: ERJ-2RKF1002X)
R420  ValueDisplayed: 10.0k  [0402]  (hidden comment: ERJ-2RKF1002X)
R421  ValueDisplayed: 10.0k  [0402L]  (hidden comment: CRCW040210K0FKED)
R429  Res_ohm: 22  [FP-CRCW020122R0FNED_0201 (0603 metric)-MFG]  (hidden comment: CRCW020122R0FNED)
R430  Res_ohm: 22  [FP-CRCW020122R0FNED_0201 (0603 metric)-MFG]  (hidden comment: CRCW020122R0FNED)
R431  Res_ohm: 22  [FP-CRCW020122R0FNED_0201 (0603 metric)-MFG]  (hidden comment: CRCW020122R0FNED)
R432  Res_ohm: 22  [FP-CRCW020122R0FNED_0201 (0603 metric)-MFG]  (hidden comment: CRCW020122R0FNED)
TP35  TESTPOINT  [TP_25MIL-SMT]  (value not drawn)  (no BOM)
TP36  TESTPOINT  [TP_25MIL-SMT]  (value not drawn)  (no BOM)
TP37  TESTPOINT  [TP_25MIL-SMT]  (value not drawn)  (no BOM)
TP38  TESTPOINT  [TP_25MIL-SMT]  (value not drawn)  (no BOM)
U61  MTFC8GAMALBH-AAT  [FP-MTFC8GAMALBH-AAT_TFBGA153-MFG]  (part A of 3)
U62  SN74LVC1G08DBVR  [DBV0005A_N]  (parts A,B of 2)

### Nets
GND: C264.2 C265.2 C266.2 C267.2 R419.2 U61.A6(VSS) U61.C4(VSSQ) U61.E7(VSS) U61.G5(VSS) U61.H10(VSS) U61.J5(VSS) U61.K8(VSS) U61.N2(VSSQ) U61.N5(VSSQ) U61.P4(VSSQ) U61.P6(VSSQ) U62.3(GND)
VSYS_3V3: C264.1 C265.1 C267.1 R420.1 R421.2 U61.C6(VCCQ) U61.E6(VCC) U61.F5(VCC) U61.J10(VCC) U61.K9(VCC) U61.M4(VCCQ) U61.N4(VCCQ) U61.P3(VCCQ) U61.P5(VCCQ) U62.5(VCC)
AM263P_EMMC0_CLK_MUX: U61.M6(CLK) ; off-sheet AM263P_EMMC0_CLK_MUX
AM263P_EMMC0_CMD_MUX: U61.M5(CMD) ; off-sheet AM263P_EMMC0_CMD_MUX
AM263P_EMMC0_D0: R429.1 U61.A3(DAT0)
AM263P_EMMC0_D0_MUX: R429.2 ; off-sheet AM263P_EMMC0_D0_MUX
AM263P_EMMC0_D1: R430.1 U61.A4(DAT1)
AM263P_EMMC0_D1_MUX: R430.2 ; off-sheet AM263P_EMMC0_D1_MUX
AM263P_EMMC0_D2: R431.1 U61.A5(DAT2)
AM263P_EMMC0_D2_MUX: R431.2 ; off-sheet AM263P_EMMC0_D2_MUX
AM263P_EMMC0_D3: R432.1 U61.B2(DAT3)
AM263P_EMMC0_D3_MUX: R432.2 ; off-sheet AM263P_EMMC0_D3_MUX
AM263P_WARMRSTN: U62.2(B) ; off-sheet AM263P_WARMRSTN
EMMC_RST: R421.1 U61.K5(~{RST}) U62.4(Y)
EMMC_RST_EN: R420.2 U62.1(A) ; off-sheet EMMC_RST_EN
NetC266_1: C266.1 U61.C2(VDDIM)
NetR419_1: R419.1 U61.H5(DS)
NetTP35_1: TP35.1 U61.B3(DAT4)
NetTP36_1: TP36.1 U61.B4(DAT5)
NetTP37_1: TP37.1 U61.B5(DAT6)
NetTP38_1: TP38.1 U61.B6(DAT7)

Not connected (* = marked no-connect by the designer): U61 A7(RFU)* E5(RFU)* E8(VSF1)* E9(VSF2)* E10(VSF3)* F10(VSF4)* G10(VSF5)* K6(RFU)* K7(RFU)* K10(VSF6)* P10(VSF7)*

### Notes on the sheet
- AM263P EMMC
- EMMC RESET LOGIC

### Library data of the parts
C264 C267 = CMP-0006221-2: as C66 on sheet PROC171_AM263P_3_OSPI_MMC
C265 = CMP-0043010-1: as C258 on sheet PROC171_AM263P_3_OSPI_MMC
C266 = CMP-0006286-2: CAP, CERM, 1 uF, 16 V, +/- 10%, X6S, 0402; Manufacturer: TDK; TaMin_C: -55°C; ESR_ohm: 0.011416; Polarized: N; SizeAreaWB_mm2: 3; Value1: 0.011416 ohm; U/M: EA; Value: 1uF; TaMax_C: 105°C; SizeZ_mm: 0.6; SizeX_mm: 1; SizeY_mm: 0.5; Cap_F: 1µF; IRMS_A: 1.483A; AEC Category: Q200
R419 R420 = CMP-0026658-1: as R6 on sheet PROC171_AM263P_2_Clock_Reset_Boot_JTAG
R421 = CMP-0025958-3: as R31 on sheet PROC171_AM263P_3_OSPI_MMC
R429-R432 = CMP-0087090-2: as R27 on sheet PROC171_AM263P_3_OSPI_MMC
TP35-TP38 = CMP-0078143-3: TEST POINT.  No entry in BOM.
U61 = CMP-0091989-1: FLASH - NAND Memory IC 64Gb (8G x 8) MMC 153-TFBGA (11.5x13); Manufacturer: Micron Technology; Standoff Height: 0.174mm; Memory Size: 8GBytes; Memory Type: FLASH,NAND; TaMax_C: +105°C; Min Supply Voltage: 2.7V; TaMin_C: -40°C; Max Supply Voltage: 3.6V; Interface: Other; SizeZ_mm: 1.1mm; AEC Qualified: No
U62 = CMP-0051588-2: as U5 on sheet PROC171_AM263P_2_Clock_Reset_Boot_JTAG

## Sheet PROC171_AM263P_5_ADC_DAC.SchDoc
size 431 x 279 mm; Date: Not shown in title block; ApprovedBy: Not shown in title block; CheckedBy: Not shown in title block; Author: Not shown in title block; CompanyName: Not shown in title block; Engineer: Not shown in title block; Organization: Not shown in title block; Address1: Not shown in title block; Address2: Not shown in title block; Address3: Not shown in title block; Address4: Not shown in title block; DocumentNumber: 10; Revision: Use project parameter SCH_Rev; SheetNumber: 10; SheetTotal: 27; PageSetup: Record=PageOptions¦CenterHorizontal=True¦CenterVertical=True¦PrintScale=1.00¦XCorrection=1.00¦YCorrection=1.00¦PrintKind=0¦BorderSize=5000000¦LeftOffset=0¦BottomOffset=0¦Orientation=2¦PaperLength=1000¦PaperWidth=1000¦Scale=100¦PaperSource=15¦PrintQuality=600¦MediaType=1¦DitherType=10¦PaperKind=Letter¦PrintScaleMode=1
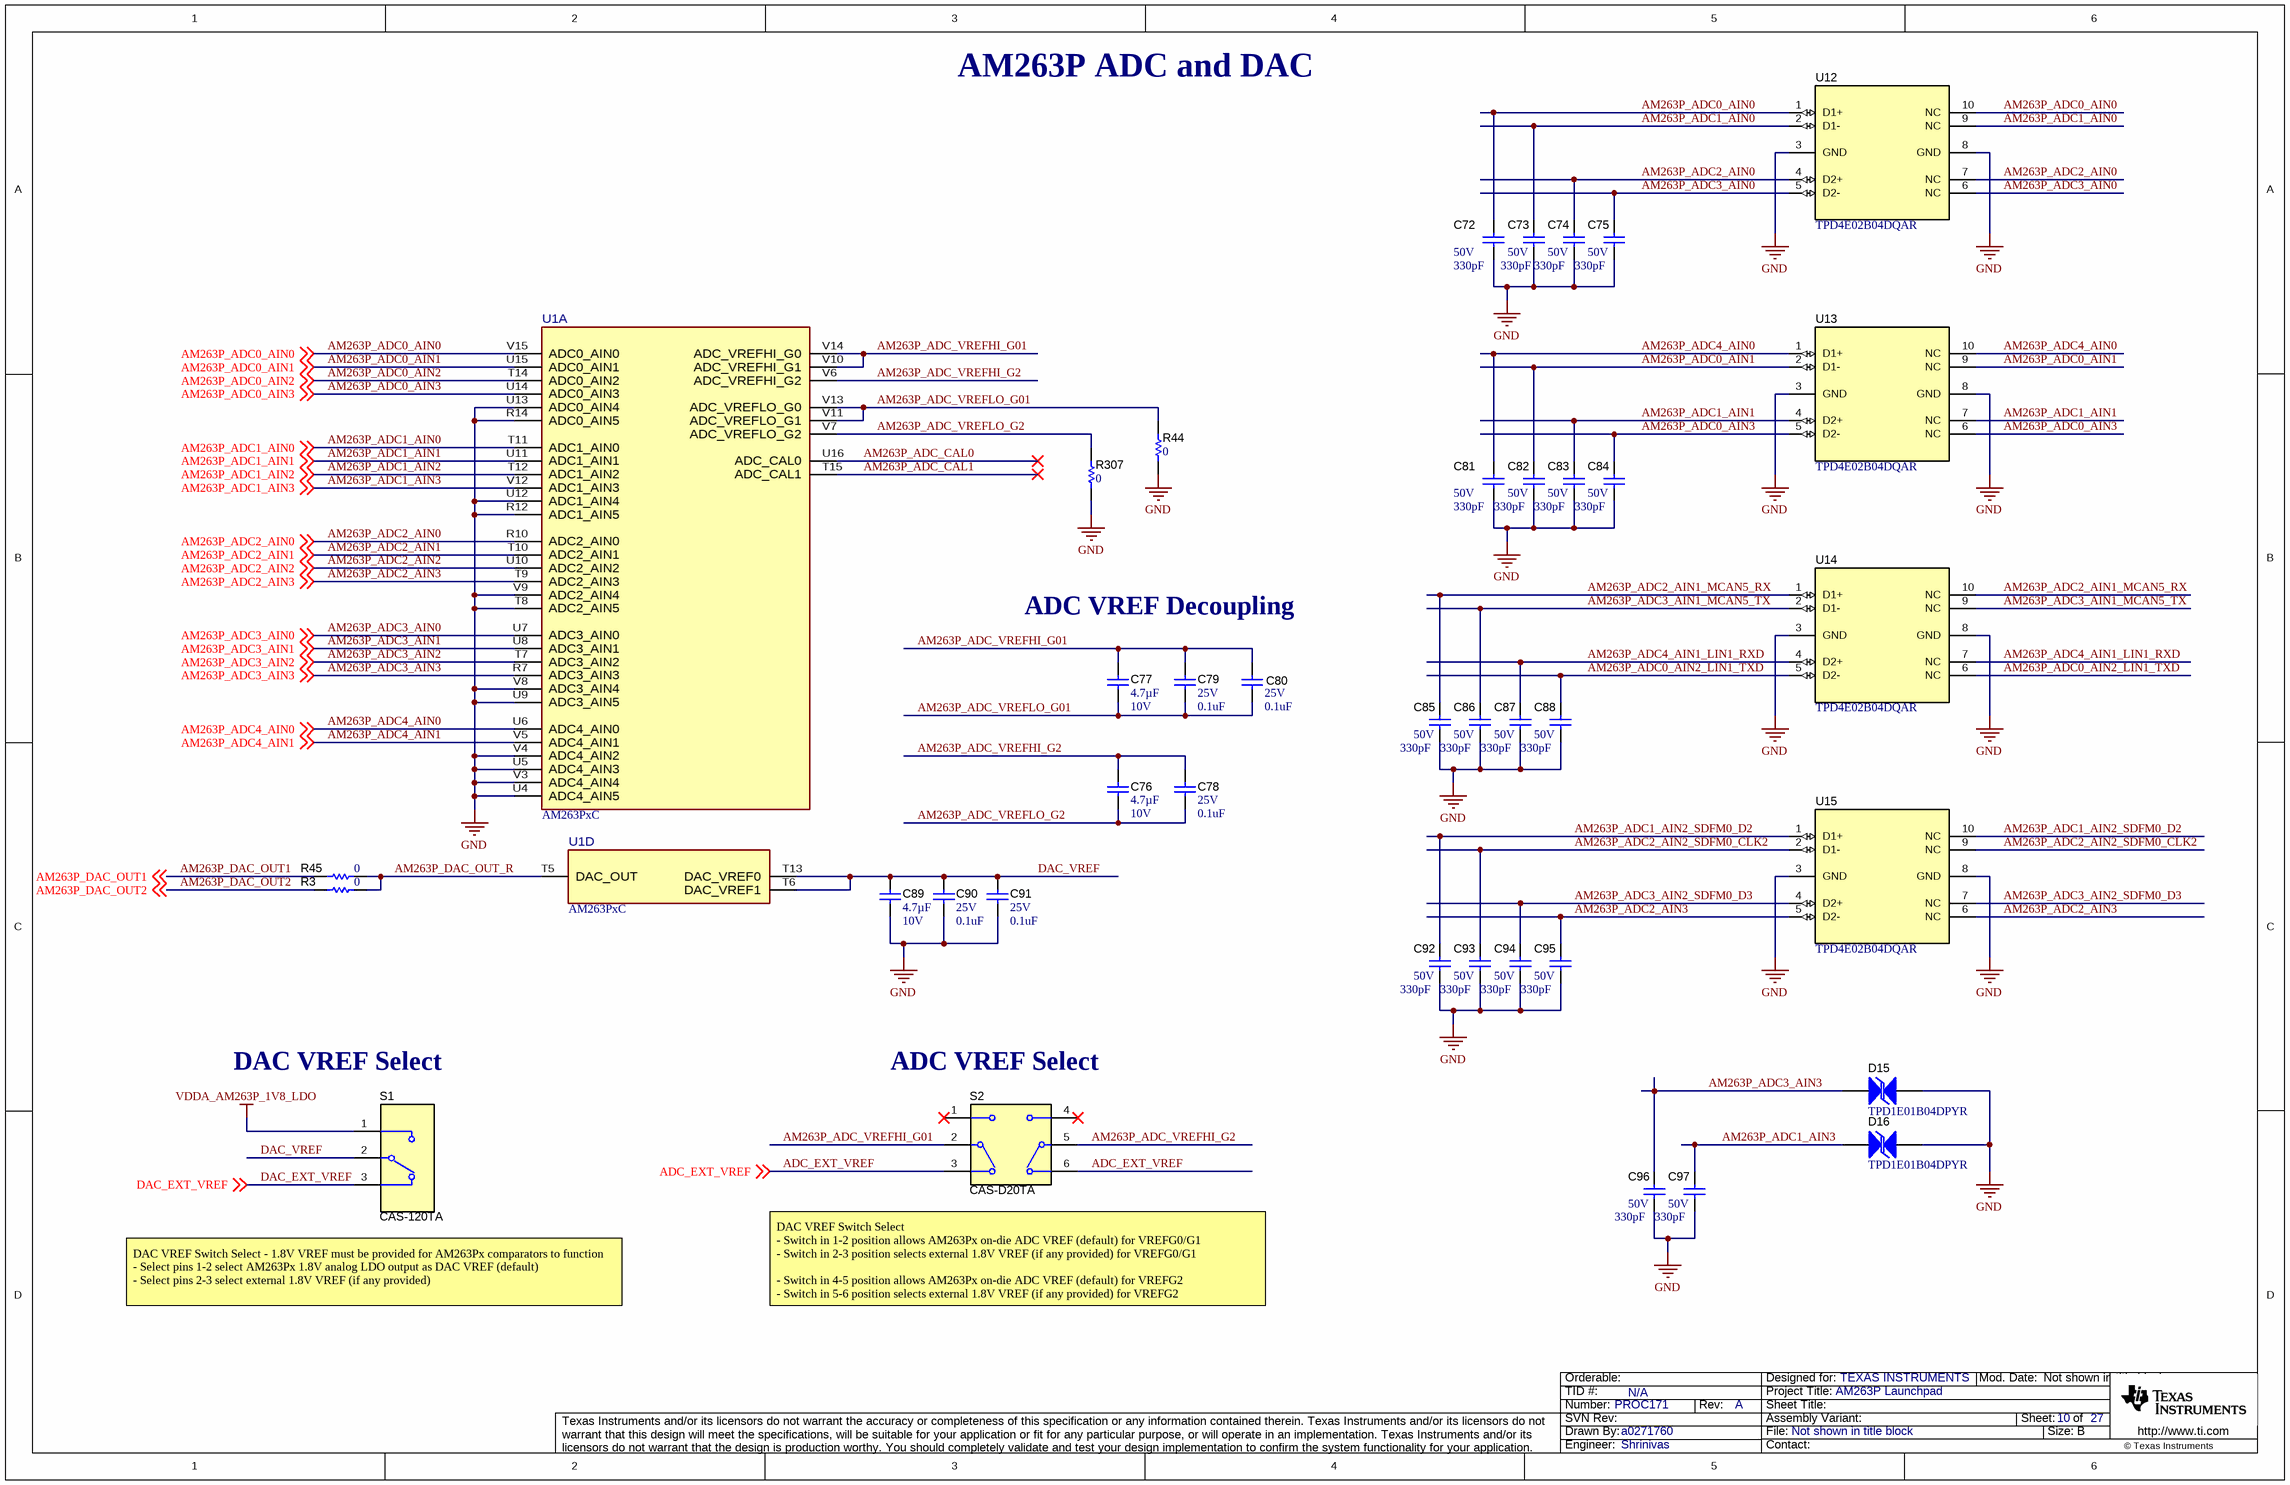
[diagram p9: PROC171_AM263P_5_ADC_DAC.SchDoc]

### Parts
C72  VDC_V: 50V  ValueDisplayed: 330pF  [0402]  (hidden comment: GRM1555C1H331JA01D)
C73  VDC_V: 50V  ValueDisplayed: 330pF  [0402]  (hidden comment: GRM1555C1H331JA01D)
C74  VDC_V: 50V  ValueDisplayed: 330pF  [0402]  (hidden comment: GRM1555C1H331JA01D)
C75  VDC_V: 50V  ValueDisplayed: 330pF  [0402]  (hidden comment: GRM1555C1H331JA01D)
C76  Cap_F: 4.7µF  VDC_V: 10V  [0603]  (hidden comment: GRM188Z71A475ME15D)
C77  Cap_F: 4.7µF  VDC_V: 10V  [0603]  (hidden comment: GRM188Z71A475ME15D)
C78  VDC_V: 25V  ValueDisplayed: 0.1uF  [0402]  (hidden comment: GRM155R71E104KE14D)
C79  VDC_V: 25V  ValueDisplayed: 0.1uF  [0402]  (hidden comment: GRM155R71E104KE14D)
C80  VDC_V: 25V  ValueDisplayed: 0.1uF  [0402]  (hidden comment: GRM155R71E104KE14D)
C81  VDC_V: 50V  ValueDisplayed: 330pF  [0402]  (hidden comment: GRM1555C1H331JA01D)
C82  VDC_V: 50V  ValueDisplayed: 330pF  [0402]  (hidden comment: GRM1555C1H331JA01D)
C83  VDC_V: 50V  ValueDisplayed: 330pF  [0402]  (hidden comment: GRM1555C1H331JA01D)
C84  VDC_V: 50V  ValueDisplayed: 330pF  [0402]  (hidden comment: GRM1555C1H331JA01D)
C85  VDC_V: 50V  ValueDisplayed: 330pF  [0402]  (hidden comment: GRM1555C1H331JA01D)
C86  VDC_V: 50V  ValueDisplayed: 330pF  [0402]  (hidden comment: GRM1555C1H331JA01D)
C87  VDC_V: 50V  ValueDisplayed: 330pF  [0402]  (hidden comment: GRM1555C1H331JA01D)
C88  VDC_V: 50V  ValueDisplayed: 330pF  [0402]  (hidden comment: GRM1555C1H331JA01D)
C89  Cap_F: 4.7µF  VDC_V: 10V  [0603]  (hidden comment: GRM188Z71A475ME15D)
C90  VDC_V: 25V  ValueDisplayed: 0.1uF  [0402]  (hidden comment: GRM155R71E104KE14D)
C91  VDC_V: 25V  ValueDisplayed: 0.1uF  [0402]  (hidden comment: GRM155R71E104KE14D)
C92  VDC_V: 50V  ValueDisplayed: 330pF  [0402]  (hidden comment: GRM1555C1H331JA01D)
C93  VDC_V: 50V  ValueDisplayed: 330pF  [0402]  (hidden comment: GRM1555C1H331JA01D)
C94  VDC_V: 50V  ValueDisplayed: 330pF  [0402]  (hidden comment: GRM1555C1H331JA01D)
C95  VDC_V: 50V  ValueDisplayed: 330pF  [0402]  (hidden comment: GRM1555C1H331JA01D)
C96  VDC_V: 50V  ValueDisplayed: 330pF  [0402]  (hidden comment: GRM1555C1H331JA01D)
C97  VDC_V: 50V  ValueDisplayed: 330pF  [0402]  (hidden comment: GRM1555C1H331JA01D)
D15  TPD1E01B04DPYR  [DPY0002A]
D16  TPD1E01B04DPYR  [DPY0002A]
R3  value 0  [0402L]  (hidden comment: ERJ-2GE0R00X)
R44  value 0  [0402L]  (hidden comment: ERJ-2GE0R00X)
R45  value 0  [0402L]  (hidden comment: ERJ-2GE0R00X)
R307  value 0  [0402L]  (hidden comment: ERJ-2GE0R00X)
S1  CAS-120TA  [SW_CAS-120TA]
S2  CAS-D20TA  [SW_CAS-D20TA]
U1  AM263PxC  [ZCZ0324A-MFG]  (parts A,D of 13)
U12  TPD4E02B04DQAR  [DQA0010A]
U13  TPD4E02B04DQAR  [DQA0010A]
U14  TPD4E02B04DQAR  [DQA0010A]
U15  TPD4E02B04DQAR  [DQA0010A]

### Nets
GND: C72.2 C73.2 C74.2 C75.2 C81.2 C82.2 C83.2 C84.2 C85.2 C86.2 C87.2 C88.2 C89.2 C90.2 C91.2 C92.2 C93.2 C94.2 C95.2 C96.2 C97.2 D15.1 D16.2 R44.1 R307.1 U1.R12(ADC1_AIN5) U1.R14(ADC0_AIN5) U1.T8(ADC2_AIN5) U1.U4(ADC4_AIN5) U1.U5(ADC4_AIN3) U1.U9(ADC3_AIN5) U1.U12(ADC1_AIN4) U1.U13(ADC0_AIN4) U1.V3(ADC4_AIN4) U1.V4(ADC4_AIN2) U1.V8(ADC3_AIN4) U1.V9(ADC2_AIN4) U12.3(GND) U12.8(GND) U13.3(GND) U13.8(GND) U14.3(GND) U14.8(GND) U15.3(GND) U15.8(GND)
VDDA_AM263P_1V8_LDO: S1.1
ADC_EXT_VREF: S2.3 S2.6 ; off-sheet ADC_EXT_VREF
AM263P_ADC0_AIN0: C72.1 U1.V15(ADC0_AIN0) U12.1(D1+) U12.10(NC) ; off-sheet AM263P_ADC0_AIN0
AM263P_ADC0_AIN1: C82.1 U1.U15(ADC0_AIN1) U13.2(D1-) U13.9(NC) ; off-sheet AM263P_ADC0_AIN1
AM263P_ADC0_AIN2: U1.T14(ADC0_AIN2) ; off-sheet AM263P_ADC0_AIN2
AM263P_ADC0_AIN2_LIN1_TXD: C88.1 U14.5(D2-) U14.6(NC)
AM263P_ADC0_AIN3: C84.1 U1.U14(ADC0_AIN3) U13.5(D2-) U13.6(NC) ; off-sheet AM263P_ADC0_AIN3
AM263P_ADC1_AIN0: C73.1 U1.T11(ADC1_AIN0) U12.2(D1-) U12.9(NC) ; off-sheet AM263P_ADC1_AIN0
AM263P_ADC1_AIN1: C83.1 U1.U11(ADC1_AIN1) U13.4(D2+) U13.7(NC) ; off-sheet AM263P_ADC1_AIN1
AM263P_ADC1_AIN2: U1.T12(ADC1_AIN2) ; off-sheet AM263P_ADC1_AIN2
AM263P_ADC1_AIN2_SDFM0_D2: C92.1 U15.1(D1+) U15.10(NC)
AM263P_ADC1_AIN3: C97.1 D16.1 U1.V12(ADC1_AIN3) ; off-sheet AM263P_ADC1_AIN3
AM263P_ADC2_AIN0: C74.1 U1.R10(ADC2_AIN0) U12.4(D2+) U12.7(NC) ; off-sheet AM263P_ADC2_AIN0
AM263P_ADC2_AIN1: U1.T10(ADC2_AIN1) ; off-sheet AM263P_ADC2_AIN1
AM263P_ADC2_AIN1_MCAN5_RX: C85.1 U14.1(D1+) U14.10(NC)
AM263P_ADC2_AIN2: U1.U10(ADC2_AIN2) ; off-sheet AM263P_ADC2_AIN2
AM263P_ADC2_AIN2_SDFM0_CLK2: C93.1 U15.2(D1-) U15.9(NC)
AM263P_ADC2_AIN3: C95.1 U1.T9(ADC2_AIN3) U15.5(D2-) U15.6(NC) ; off-sheet AM263P_ADC2_AIN3
AM263P_ADC3_AIN0: C75.1 U1.U7(ADC3_AIN0) U12.5(D2-) U12.6(NC) ; off-sheet AM263P_ADC3_AIN0
AM263P_ADC3_AIN1: U1.U8(ADC3_AIN1) ; off-sheet AM263P_ADC3_AIN1
AM263P_ADC3_AIN1_MCAN5_TX: C86.1 U14.2(D1-) U14.9(NC)
AM263P_ADC3_AIN2: U1.T7(ADC3_AIN2) ; off-sheet AM263P_ADC3_AIN2
AM263P_ADC3_AIN2_SDFM0_D3: C94.1 U15.4(D2+) U15.7(NC)
AM263P_ADC3_AIN3: C96.1 D15.2 U1.R7(ADC3_AIN3) ; off-sheet AM263P_ADC3_AIN3
AM263P_ADC4_AIN0: C81.1 U1.U6(ADC4_AIN0) U13.1(D1+) U13.10(NC) ; off-sheet AM263P_ADC4_AIN0
AM263P_ADC4_AIN1: U1.V5(ADC4_AIN1) ; off-sheet AM263P_ADC4_AIN1
AM263P_ADC4_AIN1_LIN1_RXD: C87.1 U14.4(D2+) U14.7(NC)
AM263P_ADC_CAL0: U1.U16(ADC_CAL0)
AM263P_ADC_CAL1: U1.T15(ADC_CAL1)
AM263P_ADC_VREFHI_G01: C77.1 C79.1 C80.1 S2.2(C) U1.V10(ADC_VREFHI_G1) U1.V14(ADC_VREFHI_G0)
AM263P_ADC_VREFHI_G2: C76.1 C78.1 S2.5(C) U1.V6(ADC_VREFHI_G2)
AM263P_ADC_VREFLO_G01: C77.2 C79.2 C80.2 R44.2 U1.V11(ADC_VREFLO_G1) U1.V13(ADC_VREFLO_G0)
AM263P_ADC_VREFLO_G2: C76.2 C78.2 R307.2 U1.V7(ADC_VREFLO_G2)
AM263P_DAC_OUT1: R45.1 ; off-sheet AM263P_DAC_OUT1
AM263P_DAC_OUT2: R3.1 ; off-sheet AM263P_DAC_OUT2
AM263P_DAC_OUT_R: R3.2 R45.2 U1.T5(DAC_OUT)
DAC_EXT_VREF: S1.3 ; off-sheet DAC_EXT_VREF
DAC_VREF: C89.1 C90.1 C91.1 S1.2 U1.T6(DAC_VREF1) U1.T13(DAC_VREF0)

Not connected (* = marked no-connect by the designer): S2 1* 4*

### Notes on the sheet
- AM263P ADC and DAC
- ADC VREF Decoupling
- DAC VREF Select
- (near S2) ADC VREF Select
- DAC VREF Switch Select - 1.8V VREF must be provided for AM263Px comparators to function
  - Select pins 1-2 select AM263Px 1.8V analog LDO output as DAC VREF (default)
  - Select pins 2-3 select external 1.8V VREF (if any provided)
- (near S2) DAC VREF Switch Select
  - Switch in 1-2 position allows AM263Px on-die ADC VREF (default) for VREFG0/G1
  - Switch in 2-3 position selects external 1.8V VREF (if any provided) for VREFG0/G1
  - Switch in 4-5 position allows AM263Px on-die ADC VREF (default) for VREFG2
  - Switch in 5-6 position selects external 1.8V VREF (if any provided) for VREFG2

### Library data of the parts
C72-C75 C81-C88 C92-C97 = CMP-0006456-2: CAP, CERM, 330 pF, 50 V, +/- 5%, C0G/NP0, 0402; Manufacturer: MuRata; TaMin_C: -55°C; Polarized: N; SizeAreaWB_mm2: 3; U/M: EA; Value: 330pF; TaMax_C: 125°C; SizeZ_mm: 0.6; SizeX_mm: 1; SizeY_mm: 0.5; AEC Category: Q200; Value1: Unknown
C76 C77 C89 = CMP-0007498-4: CAP, CERM, 4.7 uF, 10 V, +/- 20%, X7R, 0603; Manufacturer: MuRata; TaMin_C: -55°C; Polarized: N; SizeAreaWB_mm2: 4.68; Value1: Unknown; U/M: EA; Value: 4.7uF; TaMax_C: 125°C; SizeZ_mm: 1; SizeX_mm: 1.6; SizeY_mm: 0.8; SizeArea_mm2: 1.28; AEC Category: Q200
C78-C80 C90 C91 = CMP-0006659-2: as C69 on sheet PROC171_AM263P_3_OSPI_MMC
D15 D16 = CMP-0073602-3: 1-Channel ESD Protection Diode for USB Type-C and Thunderbolt 3, DPY0002A (X1SON-2); Alternate Manufacturer: Texas Instruments; Alternate PartNumber: TPD1E01B04DPYT; AEC Category: Q200; SizeArea_mm2: 0.6; CompType: IC; SizeAreaWB_mm2: 3.2; SizeZ_mm: 0.45; Rating: Catalog; SizeX_mm: 1.0
R3 R44 R45 R307 = CMP-0026992-3: as R4 on sheet PROC171_AM263P_2_Clock_Reset_Boot_JTAG
S1 = CMP-0002139-2: Switch, Slide, SPDT  100mA, SMT; Manufacturer: Copal Electronics; CurrentRating_mA: 100A; SwitchFunction: On-On; VDC_V: 6V; PositionCount: 1
S2 = CMP-0002233-1: Switch, Dual SPDT,  2 Pos, 0.1A, 6VDC, SMD; Manufacturer: Copal Electronics; CurrentRating_mA: 100A; SwitchFunction: On-On; VDC_V: 6V; PositionCount: 2
U1 = CMP-0001698-2: as U1 on sheet PROC171_AM263P_2_Clock_Reset_Boot_JTAG
U12-U15 = CMP-0073612-3: 4-Channel ESD Protection Diode for USB Type-C and HDMI 2.0, DQA0010A (USON-10); Alternate Manufacturer: Texas Instruments; Green_Lifecycle: Active; SizeAreaWB_mm2: 7.0; Green_REACh: Passed; SizeZ_mm: 0.55; SizeX_mm: 1.0; SizeY_mm: 2.5; CompType: IC; AEC Category: Q200; AEC Qualified: Y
